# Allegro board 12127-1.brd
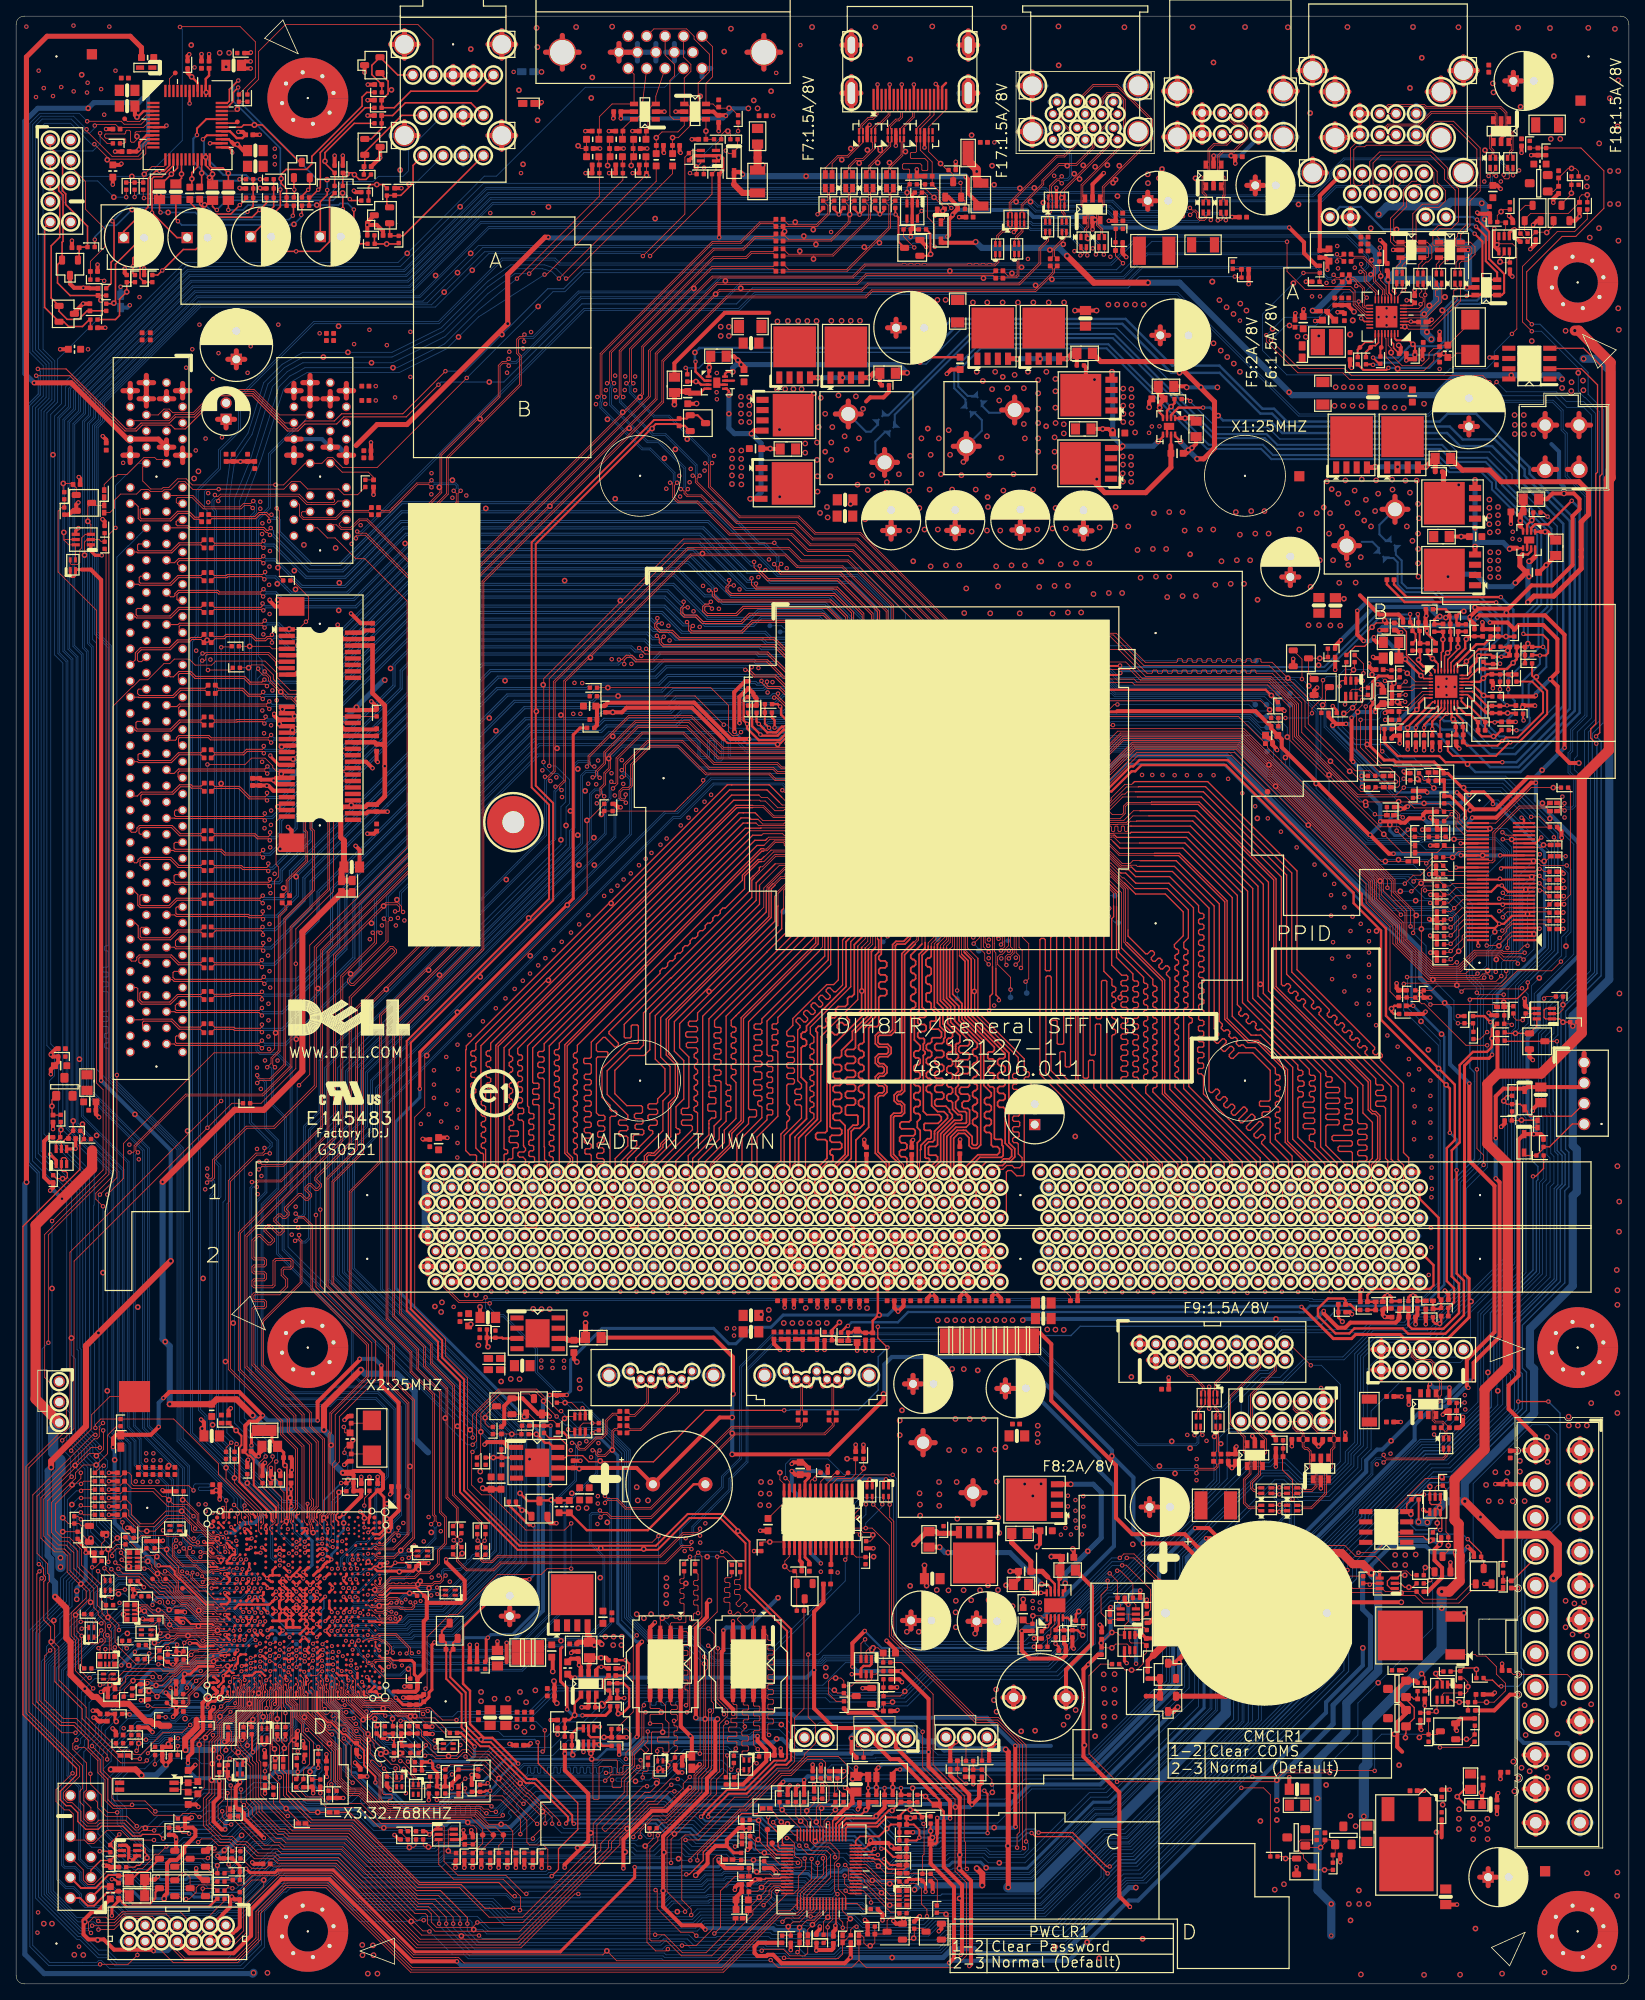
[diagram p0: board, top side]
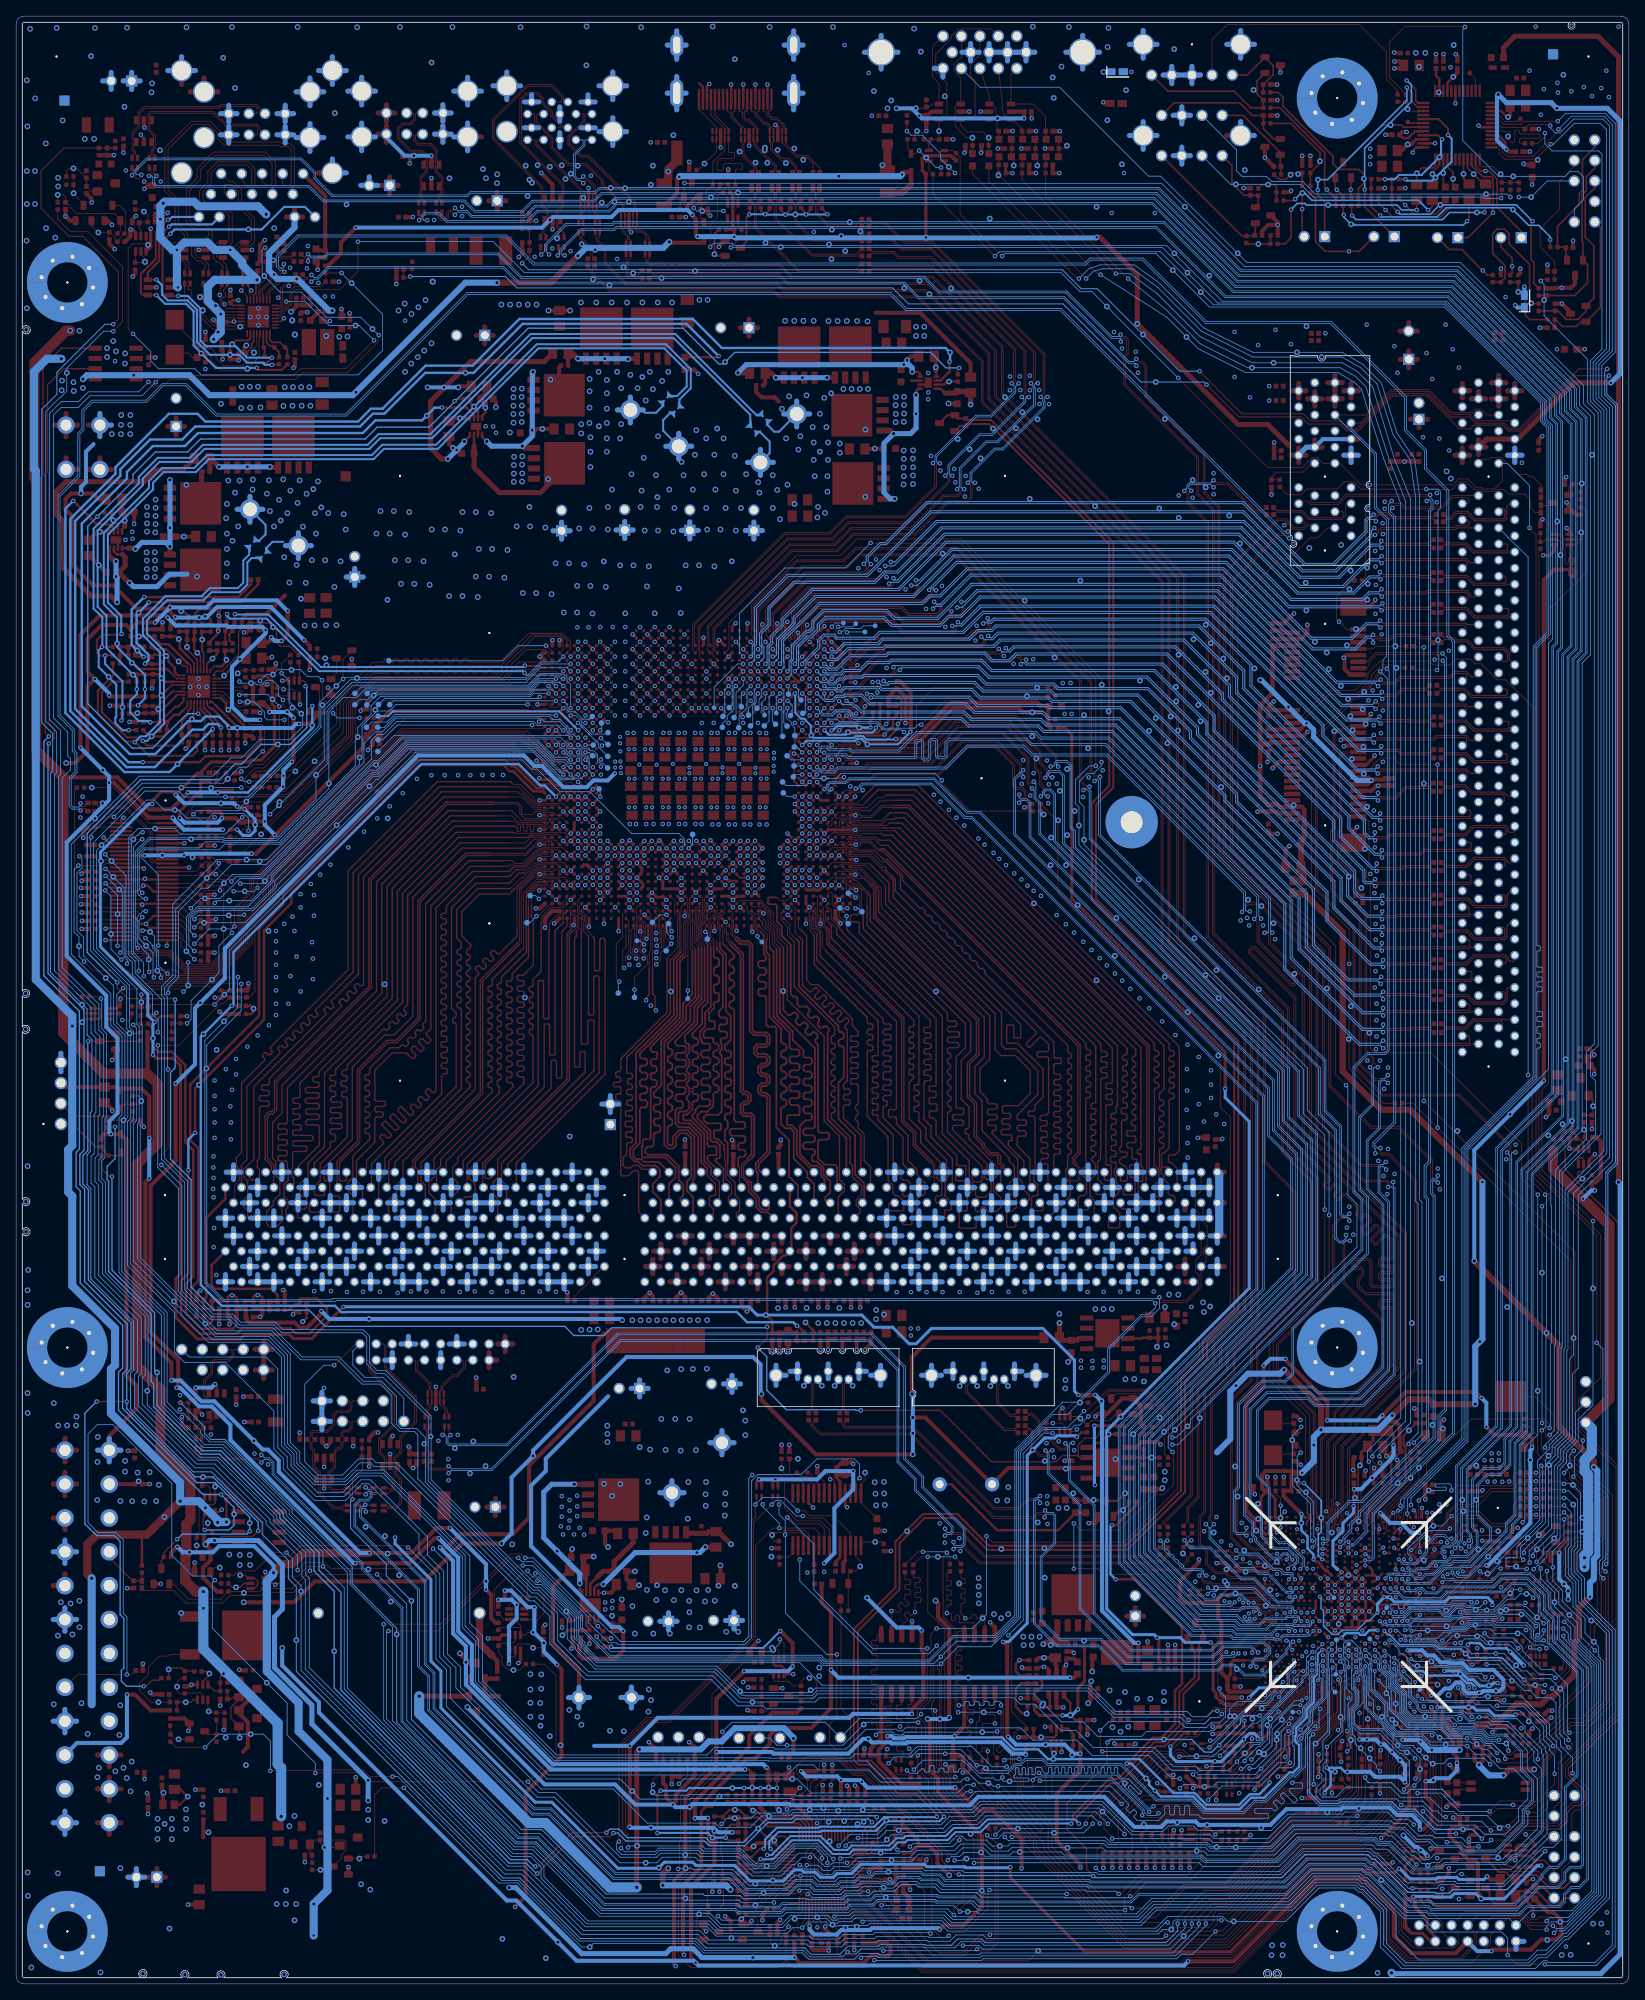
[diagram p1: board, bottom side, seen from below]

Outline 200 x 244 mm; copper layers: TOP, L2VCC, L3, BOTTOM. Coordinates in mm from the lower left corner of the outline.
Outline path: 0,243 0,1 arc(0.29,0.29) 1,0 199,0 arc(199.71,0.29) 200,1 200,243 arc(199.71,243.71) 199,244 1,244 arc(0.29,243.71) 0,243

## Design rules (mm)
net group 5MIL: nets ANTI-POP_GPIO1 EAPD_DEPOP
net group 6MIL: nets DDSP_D_TX_N0 DDSP_D_TX_N2
net group AUDIO-10: nets MIC1_VREFO_L MIC1_VREFO_R
net group CK_96M_DREF-DIFF: nets CK_96M_DREF_DN CK_96M_DREF_DP
net group CK_100M_CPU_XDP_DN: nets CK_100M_CPU_XDP_DN CK_XDP_S_DN
net group CK_100M_CPU_XDP_DP: nets CK_100M_CPU_XDP_DP CK_XDP_S_DP
net group CK_100M_DMI-DIFF: nets 100M_DMI_PCH_DN 100M_DMI_PCH_DP
net group CK_CSI_PCH-DIFF1: nets CK_CSI_PCH_IN_DN CK_CSI_PCH_IN_DP
net group CK_SATA_PCH-DIFF1: nets CK_SATA_PCH_DN CK_SATA_PCH_DP
net group DMI-8: nets DMIRCOMP XCLK_RCOMP
net group EXP_A_TX_0_C_DN: nets EXP_A_TX_0_C_DN EXP_A_TX_DN0
net group EXP_A_TX_0_C_DP: nets EXP_A_TX_0_C_DP EXP_A_TX_DP0
net group EXP_A_TX_1_C_DN: nets EXP_A_TX_1_C_DN EXP_A_TX_DN1
net group EXP_A_TX_1_C_DP: nets EXP_A_TX_1_C_DP EXP_A_TX_DP1
net group EXP_A_TX_2_C_DN: nets EXP_A_TX_2_C_DN EXP_A_TX_DN2
net group EXP_A_TX_2_C_DP: nets EXP_A_TX_2_C_DP EXP_A_TX_DP2
net group EXP_A_TX_3_C_DN: nets EXP_A_TX_3_C_DN EXP_A_TX_DN3
net group EXP_A_TX_3_C_DP: nets EXP_A_TX_3_C_DP EXP_A_TX_DP3
net group EXP_A_TX_4_C_DN: nets EXP_A_TX_4_C_DN EXP_A_TX_DN4
net group EXP_A_TX_4_C_DP: nets EXP_A_TX_4_C_DP EXP_A_TX_DP4
net group EXP_A_TX_5_C_DN: nets EXP_A_TX_5_C_DN EXP_A_TX_DN5
net group EXP_A_TX_5_C_DP: nets EXP_A_TX_5_C_DP EXP_A_TX_DP5
net group EXP_A_TX_6_C_DN: nets EXP_A_TX_6_C_DN EXP_A_TX_DN6
net group EXP_A_TX_6_C_DP: nets EXP_A_TX_6_C_DP EXP_A_TX_DP6
net group EXP_A_TX_7_C_DN: nets EXP_A_TX_7_C_DN EXP_A_TX_DN7
net group EXP_A_TX_7_C_DP: nets EXP_A_TX_7_C_DP EXP_A_TX_DP7
net group EXP_A_TX_8_C_DN: nets EXP_A_TX_8_C_DN EXP_A_TX_DN8
net group EXP_A_TX_8_C_DP: nets EXP_A_TX_8_C_DP EXP_A_TX_DP8
net group EXP_A_TX_9_C_DN: nets EXP_A_TX_9_C_DN EXP_A_TX_DN9
net group EXP_A_TX_9_C_DP: nets EXP_A_TX_9_C_DP EXP_A_TX_DP9
net group EXP_A_TX_10_C_DN: nets EXP_A_TX_10_C_DN EXP_A_TX_DN10
net group EXP_A_TX_10_C_DP: nets EXP_A_TX_10_C_DP EXP_A_TX_DP10
net group EXP_A_TX_11_C_DN: nets EXP_A_TX_11_C_DN EXP_A_TX_DN11
net group EXP_A_TX_11_C_DP: nets EXP_A_TX_11_C_DP EXP_A_TX_DP11
net group EXP_A_TX_12_C_DN: nets EXP_A_TX_12_C_DN EXP_A_TX_DN12
net group EXP_A_TX_12_C_DP: nets EXP_A_TX_12_C_DP EXP_A_TX_DP12
net group EXP_A_TX_13_C_DN: nets EXP_A_TX_13_C_DN EXP_A_TX_DN13
net group EXP_A_TX_13_C_DP: nets EXP_A_TX_13_C_DP EXP_A_TX_DP13
net group EXP_A_TX_14_C_DN: nets EXP_A_TX_14_C_DN EXP_A_TX_DN14
net group EXP_A_TX_14_C_DP: nets EXP_A_TX_14_C_DP EXP_A_TX_DP14
net group EXP_A_TX_15_C_DN: nets EXP_A_TX_15_C_DN EXP_A_TX_DN15
net group EXP_A_TX_15_C_DP: nets EXP_A_TX_15_C_DP EXP_A_TX_DP15
net group FAN_SYS-6.5: nets SYS_FAN_CTRL_SIO SYS_FAN_TACH_SIO
net group LAN_MDI1_C-DIFF1: nets LAN_MDI1_DN_C LAN_MDI1_DP_C
net group MG-CK-DP: nets CK_DP_DN CK_DP_DP
net group MG-CK_DPNS_R: nets CK_DPNS_R_DN CK_DPNS_R_DP
net group MG-CK_GLAN: nets CK_GLAN_DN CK_GLAN_DP
net group MG-CK_PCIE_1PCIEX1: nets CK_PCIE_1PCIEX1_DN CK_PCIE_1PCIEX1_DP
net group MG-CK_PCIEX1_WLAN: nets CK_PCIEX1_WLAN_DN CK_PCIEX1_WLAN_DP
net group MG-CK_PE_100M_16PORT: nets CK_PE_100M_16PORT_DN CK_PE_100M_16PORT_DP
net group MG-CK_PE_100M_MCP: nets CK_PE_100M_MCP_DN CK_PE_100M_MCP_DP
net group MG-DDR-A-DQS0: nets M_DQS_A_DN0 M_DQS_A_DP0
net group MG-DDR-A-DQS1: nets M_DQS_A_DN1 M_DQS_A_DP1
net group MG-DDR-A-DQS2: nets M_DQS_A_DN2 M_DQS_A_DP2
net group MG-DDR-A-DQS3: nets M_DQS_A_DN3 M_DQS_A_DP3
net group MG-DDR-A-DQS4: nets M_DQS_A_DN4 M_DQS_A_DP4
net group MG-DDR-A-DQS5: nets M_DQS_A_DN5 M_DQS_A_DP5
net group MG-DDR-A-DQS6: nets M_DQS_A_DN6 M_DQS_A_DP6
net group MG-DDR-A-DQS7: nets M_DQS_A_DN7 M_DQS_A_DP7
net group MG-DDR-B-DQ0: nets M_DQS_B_DN0 M_DQS_B_DP0
net group MG-DDR-B-DQ1: nets M_DQS_B_DN1 M_DQS_B_DP1
net group MG-DDR-B-DQ2: nets M_DQS_B_DN2 M_DQS_B_DP2
net group MG-DDR-B-DQ3: nets M_DQS_B_DN3 M_DQS_B_DP3
net group MG-DDR-B-DQ4: nets M_DQS_B_DN4 M_DQS_B_DP4
net group MG-DDR-B-DQ5: nets M_DQS_B_DN5 M_DQS_B_DP5
net group MG-DDR-B-DQ6: nets M_DQS_B_DN6 M_DQS_B_DP6
net group MG-DDR-B-DQ7: nets M_DQS_B_DN7 M_DQS_B_DP7
net group MG-LAN0: nets LAN_MDI0_DN LAN_MDI0_DP
net group MG-LAN1: nets LAN_MDI1_DN LAN_MDI1_DP
net group MG-LAN2: nets LAN_MDI2_DN LAN_MDI2_DP
net group MG-LAN3: nets LAN_MDI3_DN LAN_MDI3_DP
net group MG-LAN-MDI3: nets LAN_MDI3_DN_C LAN_MDI3_DP_C
net group MG-LAN_MDI1: nets LAN_MDI0_DN_C LAN_MDI0_DP_C
net group MG-LAN_MDI2: nets LAN_MDI2_DN_C LAN_MDI2_DP_C
net group MG-PCIE-RX-0: nets EXP_A_RX_DN0 EXP_A_RX_DP0
net group MG-PCIE-RX-1: nets EXP_A_RX_DN1 EXP_A_RX_DP1
net group MG-PCIE-RX-2: nets EXP_A_RX_DN2 EXP_A_RX_DP2
net group MG-PCIE-RX-3: nets EXP_A_RX_DN3 EXP_A_RX_DP3
net group MG-PCIE-RX-4: nets EXP_A_RX_DN4 EXP_A_RX_DP4
net group MG-PCIE-RX-5: nets EXP_A_RX_DN5 EXP_A_RX_DP5
net group MG-PCIE-RX-6: nets EXP_A_RX_DN6 EXP_A_RX_DP6
net group MG-PCIE-RX-7: nets EXP_A_RX_DN7 EXP_A_RX_DP7
net group MG-PCIE-RX-8: nets EXP_A_RX_DN8 EXP_A_RX_DP8
net group MG-PCIE-RX-9: nets EXP_A_RX_DN9 EXP_A_RX_DP9
net group MG-PCIE-RX-10: nets EXP_A_RX_DN10 EXP_A_RX_DP10
net group MG-PCIE-RX-11: nets EXP_A_RX_DN11 EXP_A_RX_DP11
net group MG-PCIE-RX-12: nets EXP_A_RX_DN12 EXP_A_RX_DP12
net group MG-PCIE-RX-13: nets EXP_A_RX_DN13 EXP_A_RX_DP13
net group MG-PCIE-RX-14: nets EXP_A_RX_DN14 EXP_A_RX_DP14
net group MG-PCIE-RX-15: nets EXP_A_RX_DN15 EXP_A_RX_DP15
net group MINI_CARD-4: nets MINI_CLKREQ#_WLAN MINI_CLKREQ#_WLAN_C
net group POWER_CPU_10_5-10: nets V_1P05_PECI_VCOM V_VCCIOA_LOAD
net group PWM_CSN4: nets PWM_CSN4 VCC
net group SIO_GND: nets SIO_VIN0 SIO_VIN1
net group 5MIL-1: nets +5V_VGA V_5P0_CONN_CRT_L V_5P0_HDMI_CONN V_5P0_HDMI_CONN_L
net group 6.5MS: nets M_CAS_A_N M_MAA_A0 M_MAA_A1 M_MAA_A2 M_MAA_A3 M_MAA_A4 M_MAA_A5 M_MAA_A6 M_MAA_A7 M_MAA_A8 M_MAA_A9 M_MAA_A10 M_MAA_A11 M_MAA_A12 M_MAA_A13 M_MAA_A14 M_MAA_A15 M_RAS_A_N M_SBS_A0 M_SBS_A1 M_SBS_A2 M_WE_A_N
net group 7MIL: nets FP_AUD_DETECT
net group 7MIL-1: nets FWH_ID0 INIT_3V L_AD0 L_AD0_R L_AD1 L_AD1_R L_AD2 L_AD2_R L_AD3 L_AD3_R L_FRAME_N L_FRAME_N_R LPC_DRQ0_N LPC_DRQ1_N SER_IRQ
net group 8MIL: nets SLP_SUS_FET SLP_SUS_FET_L SLP_SUSB SLP_SUSB_L_2 SUS_WARN_5VDUAL SUS_WARN_5VDUAL_L SUS_WARNB SUS_WARNB_L SUS_WARNB_R SUSACK_N
net group 9.5MS: nets M_ODT_A0 M_ODT_A1 M_SCKE_A0 M_SCKE_A1 M_SCS_A_N0 M_SCS_A_N1
net group 9.5MS-1: nets M_ODT_B0 M_ODT_B1 M_SCKE_B0 M_SCKE_B1 M_SCS_B_N0 M_SCS_B_N1
net group 10MIL: nets AUD_LINK_BCLK AUD_LINK_BCLK_R AUD_LINK_RST_N AUD_LINK_RST_R_N AUD_LINK_SDIN AUD_LINK_SDIN_1 AUD_LINK_SDO AUD_LINK_SDO_R AUD_LINK_SDO_R1 AUD_LINK_SYNC AUD_LINK_SYNC_R COPEN* CPU_THERMDA FRONT_JD LINE2_JD LINEIN_JD MIC1_JD MIC2_JD SENSE_A SENSE_B SYS_TEMP_SIO TSD-_1 TSD-_2
net group 12MIL: nets DIMM_CA_CPU_VREF_A DIMM_CA_CPU_VREF_RC DIMM_CA_VREF_A DIMM_CA_VREF_A_L DIMM_DQ_CPU_VREF_A DIMM_DQ_VREF_A DIMM_DQ_VREF_A_L DMI_IT_MR_DN0 DMI_IT_MR_DN1 DMI_IT_MR_DN2 DMI_IT_MR_DN3 DMI_IT_MR_DP0 DMI_IT_MR_DP1 DMI_IT_MR_DP2 DMI_IT_MR_DP3 DMI_MT_IR_DN0 DMI_MT_IR_DN1 DMI_MT_IR_DN2 DMI_MT_IR_DN3 DMI_MT_IR_DP0 DMI_MT_IR_DP1 DMI_MT_IR_DP2 DMI_MT_IR_DP3 FDI_TX_DN0 FDI_TX_DN1 FDI_TX_DP0 FDI_TX_DP1 USB_EXT2_DN10 USB_EXT2_DN11 USB_EXT2_DP10 USB_EXT2_DP11 USB_EXT_DN0 USB_EXT_DN1 USB_EXT_DN2 USB_EXT_DN3 USB_EXT_DN4 USB_EXT_DN8 USB_EXT_DN9 USB_EXT_DN10 USB_EXT_DN11 USB_EXT_DP0 USB_EXT_DP1 USB_EXT_DP2 USB_EXT_DP3 USB_EXT_DP4 USB_EXT_DP8 USB_EXT_DP9 USB_EXT_DP10 USB_EXT_DP11 USB_PCH_DN0 USB_PCH_DN1 USB_PCH_DN2 USB_PCH_DN3 USB_PCH_DN4 USB_PCH_DN5 USB_PCH_DN8 USB_PCH_DN9 USB_PCH_DN10 USB_PCH_DN11 USB_PCH_DP0 USB_PCH_DP1 USB_PCH_DP2 USB_PCH_DP3 USB_PCH_DP4 USB_PCH_DP5 USB_PCH_DP8 USB_PCH_DP9 USB_PCH_DP10 USB_PCH_DP11
net group 15MIL: nets DDSP_C_TX_DN_0 DDSP_C_TX_DN_1 DDSP_C_TX_DN_2 DDSP_C_TX_DN_3 DDSP_C_TX_DP_0 DDSP_C_TX_DP_1 DDSP_C_TX_DP_2 DDSP_C_TX_DP_3 HDMI_LANE0_DN HDMI_LANE0_DN_C HDMI_LANE0_DP HDMI_LANE0_DP_C HDMI_LANE1_DN HDMI_LANE1_DN_C HDMI_LANE1_DP HDMI_LANE1_DP_C HDMI_LANE2_DN HDMI_LANE2_DN_C HDMI_LANE2_DP HDMI_LANE2_DP_C HDMI_LANE3_DN HDMI_LANE3_DN_C HDMI_LANE3_DP HDMI_LANE3_DP_C HSI_DN3 HSI_DN4 HSI_DN5 HSI_DP3 HSI_DP4 HSI_DP5 HSI_LAN_DN4_R HSI_LAN_DP4_R HSO_C_DN3 HSO_C_DN4 HSO_C_DN5 HSO_C_DP3 HSO_C_DP4 HSO_C_DP5 HSO_C_LAN_DN4 HSO_C_LAN_DP4 HSO_DN3 HSO_DN5 HSO_DP3 HSO_DP5 TPEV_CFG_RCOMP
net group 18.5MS: nets M_DATA_A0 M_DATA_A1 M_DATA_A2 M_DATA_A3 M_DATA_A4 M_DATA_A5 M_DATA_A6 M_DATA_A7 M_DATA_A8 M_DATA_A9 M_DATA_A10 M_DATA_A11 M_DATA_A12 M_DATA_A13 M_DATA_A14 M_DATA_A15 M_DATA_A16 M_DATA_A17 M_DATA_A18 M_DATA_A19 M_DATA_A20 M_DATA_A21 M_DATA_A22 M_DATA_A23 M_DATA_A24 M_DATA_A25 M_DATA_A26 M_DATA_A27 M_DATA_A28 M_DATA_A29 M_DATA_A30 M_DATA_A31 M_DATA_A32 M_DATA_A33 M_DATA_A34 M_DATA_A35 M_DATA_A36 M_DATA_A37 M_DATA_A38 M_DATA_A39 M_DATA_A40 M_DATA_A41 M_DATA_A42 M_DATA_A43 M_DATA_A44 M_DATA_A45 M_DATA_A46 M_DATA_A47 M_DATA_A48 M_DATA_A49 M_DATA_A50 M_DATA_A51 M_DATA_A52 M_DATA_A53 M_DATA_A54 M_DATA_A55 M_DATA_A56 M_DATA_A57 M_DATA_A58 M_DATA_A59 M_DATA_A60 M_DATA_A61 M_DATA_A62 M_DATA_A63
net group 20MIL: nets BLUE_CRT CSN1 CSN2 CSN3 CSP1 CSP2 CSP3 FRONT_USB3_RX2+ FRONT_USB3_RX2- FRONT_USB3_TX2+ FRONT_USB3_TX2- GREEN_CRT REAR_USB3_RX0+ REAR_USB3_RX0- REAR_USB3_RX1+ REAR_USB3_RX1- REAR_USB3_TX0+ REAR_USB3_TX0- REAR_USB3_TX1+ REAR_USB3_TX1- RED_CRT SATA_RXN0_C SATA_RXN1_C SATA_RXP0_C SATA_RXP1_C SATA_TXN0_C SATA_TXN1_C SATA_TXP0_C SATA_TXP1_C SATAHDR_RX_DN0 SATAHDR_RX_DN1 SATAHDR_RX_DP0 SATAHDR_RX_DP1 SATAHDR_TX_DN0 SATAHDR_TX_DN1 SATAHDR_TX_DP0 SATAHDR_TX_DP1 USB3_RX0_DN USB3_RX0_DP USB3_RX1_DN USB3_RX1_DP USB3_RX2_DN USB3_RX2_DN_P USB3_RX2_DP USB3_RX2_DP_P USB3_TX0_C_DN USB3_TX0_C_DP USB3_TX0_EMI_DN USB3_TX0_EMI_DP USB3_TX1_C_DN USB3_TX1_C_DP USB3_TX1_EMI_DN USB3_TX1_EMI_DP USB3_TX2_C_DN USB3_TX2_C_DN_P USB3_TX2_C_DP USB3_TX2_C_DP_P USB3_TX2_EMI_DN USB3_TX2_EMI_DP VCC_SENSE VGA_BLUE VGA_BLUE_C_L VGA_GREEN VGA_GREEN_C_L VGA_RED VGA_RED_C_L VSS_SENSE
net group 40MIL: nets MEM_LX PWM1_LX PWM2_LX PWM3_LX
net group AUDIO-8: nets AUD_IN_L AUD_IN_LL AUD_IN_LL_1 AUD_IN_R AUD_IN_RR AUD_IN_RR_1 AUD_MIC2_L AUD_MIC2_L_C AUD_MIC2_R AUD_MIC2_R_C AUD_MIC_2L AUD_MIC_2R AUDAMPIN_L AUDAMPIN_L_C AUDAMPIN_R AUDAMPIN_R_C AUDIN_L AUDIN_R FB_AUDOUT_L FB_AUDOUT_R FB_AUDOUTR_L FB_AUDOUTR_R FP_MIC1_L FP_MIC1_LL FP_MIC1_LL_1 FP_MIC1_R FP_MIC1_RR FP_MIC1_RR_1 FP_MICVREF_D1 FP_MICVREF_D2 FP_OUT_L FP_OUT_L_C FP_OUT_R FP_OUT_R_C FP_OUTR_L FP_OUTR_LL FP_OUTR_R FP_OUTR_RR LINE2_VREFO MIC1_L MIC1_R MIC2-VREFO MIC2_LL MIC2_RR
net group CLOCK-4: nets CK_14M_FLEX3 CK_14M_TPM CK_33M_PCI0 CK_33M_PCI1 CK_33M_PCI2 CK_33M_PCI3 CK_48M_PCH CK_48M_SIO2 CK_P_33M_LPCP80 CK_P_33M_SIO CK_P_33M_TPM CK_PCH_33M_FB CK_REFCLK_PCH SUSCLK
net group CPU-4: nets DISP_UTIL_CPU H_PM_SYNC_0 H_PRDY_N H_PREQ_N H_SKTOCC_N H_TCK H_TDI H_TDO H_TMS H_TRST_N HSW_PCUDEBUG_0 HSW_PCUDEBUG_1 HSW_PCUDEBUG_2 HSW_PCUDEBUG_3 HSW_PCUDEBUG_4 HSW_PCUDEBUG_5 HSW_PCUDEBUG_6 HSW_PCUDEBUG_7 HSW_PCUDEBUG_8 HSW_PCUDEBUG_9 HSW_PCUDEBUG_10 HSW_PCUDEBUG_11 HSW_PCUDEBUG_12 HSW_PCUDEBUG_13 HSW_PCUDEBUG_14 HSW_PCUDEBUG_15 HSW_PCUSTB_0_DN HSW_PCUSTB_0_DP HSW_PCUSTB_1_DN HSW_PCUSTB_1_DP HSW_STRAP_13 HSW_XDP_MBP_0 HSW_XDP_MBP_1 PRIVACY_MSR_EN_N PWR_DEBUG TESTLOW_1 TESTLOW_2 VCCST_PWRGD XDP_PWR_DEBUG
net group DDR3_B-6.5MW: nets M_DATA_B0 M_DATA_B1 M_DATA_B2 M_DATA_B3 M_DATA_B4 M_DATA_B5 M_DATA_B6 M_DATA_B7 M_DATA_B8 M_DATA_B9 M_DATA_B10 M_DATA_B11 M_DATA_B12 M_DATA_B13 M_DATA_B14 M_DATA_B15 M_DATA_B16 M_DATA_B17 M_DATA_B18 M_DATA_B19 M_DATA_B20 M_DATA_B21 M_DATA_B22 M_DATA_B23 M_DATA_B24 M_DATA_B25 M_DATA_B26 M_DATA_B27 M_DATA_B28 M_DATA_B29 M_DATA_B30 M_DATA_B31 M_DATA_B32 M_DATA_B33 M_DATA_B34 M_DATA_B35 M_DATA_B36 M_DATA_B37 M_DATA_B38 M_DATA_B39 M_DATA_B40 M_DATA_B41 M_DATA_B42 M_DATA_B43 M_DATA_B44 M_DATA_B45 M_DATA_B46 M_DATA_B47 M_DATA_B48 M_DATA_B49 M_DATA_B50 M_DATA_B51 M_DATA_B52 M_DATA_B53 M_DATA_B54 M_DATA_B55 M_DATA_B56 M_DATA_B57 M_DATA_B58 M_DATA_B59 M_DATA_B60 M_DATA_B61 M_DATA_B62 M_DATA_B63
net group DDR3_B-8.5MW: nets M_CAS_B_N M_MAA_B0 M_MAA_B1 M_MAA_B2 M_MAA_B3 M_MAA_B4 M_MAA_B5 M_MAA_B6 M_MAA_B7 M_MAA_B8 M_MAA_B9 M_MAA_B10 M_MAA_B11 M_MAA_B12 M_MAA_B13 M_MAA_B14 M_MAA_B15 M_RAS_B_N M_SBS_B0 M_SBS_B1 M_SBS_B2 M_WE_B_N
net group DDR3_B-12: nets DIMM_DQ_CPU_VREF_B DIMM_DQ_CPU_VREF_B_RC DIMM_DQ_CPU_VREF_RC DIMM_DQ_VREF_B DIMM_DQ_VREF_B_L
net group DDR_RCOMP-12: nets DDR_RCOMP_0 DDR_RCOMP_1 DDR_RCOMP_2
net group DISPLAY-4: nets 5VDDCCL 5VDDCCL_R 5VDDCDA 5VDDCDA_R DDPC_CTRL_CLK DDPC_CTRL_CLK_CONN DDPC_CTRL_DATA DDPC_CTRL_DATA_CONN DDSP_C_HPD DDSP_C_HPD_CONN VCC5_DDC_HDMI VGA_DACREFSET VGA_DDC_PU VGA_HSYNC_3V VGA_HSYNC_3V_L VGA_HSYNC_3V_R VGA_PCH_DDCSCL VGA_PCH_DDCSDA VGA_VSYNC_3V VGA_VSYNC_3V_L VGA_VSYNC_3V_R
net group DP_COMP-12: nets DP_COMP
net group DUAL_POWER-6.5: nets 5VDUAL_NCH 5VDUAL_PCH 5VDUAL_PCH_R BL_CUT2 BV_5VDUAL_BACKFEED_CUT_L BV_Q49_PIN5 DUAL_V_1 DUAL_V_AND DUAL_V_AND_R DUAL_V_U DUAL_V_U_AND DUAL_V_U_INV_R L_BACKFEED_CUT LATCHED_BACKFEED_CUT MINI_POWER_CTRL MINI_POWER_CTRL_1 MINI_POWER_CTRL_2 MINI_POWER_CTRL_3 VREG_PCIAUX_PCH_1
net group FAN_CPU-6.5: nets CPU_FAN_CTRL_CONN CPU_FAN_CTRL_SIO CPU_FAN_TACH_1 CPU_FAN_TACH_L CPU_FAN_TACH_SIO
net group FDI-4: nets FDI_INT
net group FDI-8: nets FDI_RCOMP
net group GND-20: nets AGND AUD_REGREF AUDIO_VREF CPU_VSS_T8 GND JDREF SIO_GND V_1P5_STBY_INT
net group GPIO_4: nets W1_DETECT_USB_R
net group GPIO_4-4: nets BOARD_ID_0 BOARD_ID_1 BT_RADIO_CL CHASSIS_ID_0 CHASSIS_ID_1 DUAL_V FB_USBF1_DET FB_USBF2_DET FDI_CSYNC FP_AUDIO_PRESENCE*_C HDMI_DETECT IGC_EN_N IO_SMI_N LAN_DISABLE_N LANCLK_REQ_N LANCLK_REQ_U_N LANWAKE_N LATCHED_BACKFEED_CUT_R LPC_PME_N ME_CNTL ME_CNTL_1 ME_CNTL_2 MTST_ID P_PME# PCH_CONFIG_JUMPER PCH_GP69 PCH_GPIO16 PCIEX1_PRSNT2_N PECI_REQ_N PW_CLEAR QF2_1 QF2_2 RST1# SATA1GP SATA2GP SATA3GP SOP_ENABLE_GP33 SST_CTL_R TD_IREF USB_PWR_CRL1 USB_PWR_CRL1_B1 USB_PWR_CRL2 USB_PWR_CRL2_B1 VGA_DET W1_DETECT_USB WIFI_RF_EN
net group KBMS-4: nets KCLK KDAT MCLK MDAT
net group LAN-4: nets RTL_ISOLATE RTL_ISOLATE_N RTL_ISOLATE_R
net group LAN-10: nets LAN_RSET
net group LAN-10.5: nets LINK_ACTIVITY LINK_ACTIVITY_N SPEED_100 SPEED_100_N SPEED_1000 SPEED_1000_N
net group MG-DDR-A-CLK: nets CK_M_DDR0_A_DP CK_M_DDR1_A_DN CK_M_DDR1_A_DP
net group MG-DDR-A-CTRL-CLK: nets CK_M_DDR0_A_DN
net group MG-DDR-B-CLK: nets CK_M_DDR0_B_DP CK_M_DDR1_B_DN CK_M_DDR1_B_DP
net group MG-DDR-B-CTRL-CLK: nets CK_M_DDR0_B_DN
net group MSATA-4: nets CLINK_CLK CLINK_DATA CLINK_RST_N
net group OSCILLATION-4: nets LAN_XTALI LAN_XTALO PCH_RTCRST_DOWN PCH_RTCX1 PCH_RTCX2 XTAL_25M_PCH_IN XTAL_25M_PCH_OUT
net group PCH-4: nets CPU_THERMTRIP_N DSWVRMEN FP_RST_DBR_N FP_RST_PCH_N H_THERMTRIP_N KBRST_N MINI1_WAKE# PCH_GP8 PCH_GP15 PCH_GP44 PCH_GP45 PCH_GP70_PU PCH_GP71_PU PCH_GP72_PU PCH_GP74_PU PCH_INTRUDER_N PCH_INTVRMEN PCH_MEPWROK_R PCH_RI PCH_RTCRST_PULLUP PCH_SIO_DPWROK PCH_SIO_DPWROK_1 PCH_SRTCRSTB_PULLUP PCH_SYSPWROK PCIEX16_PRSNT2_N PLTRST_MINI_N PWRGD_3V RSMRST* RSMRST*_R RSMRST_SIO_N SB_PWR_ON_R SW_ON_N VR_READY WAKE_N XDP_PLTRST_N XDP_VR_READY
net group PCI-4: nets P_GNT_N1 P_GNT_N2 P_GNT_N3 P_INTA_N P_INTB_N P_INTC_N P_INTD_N P_INTH_N P_REQ_N1 P_REQ_N2 P_REQ_N3
net group PCI-8: nets PCIE_RCOMP
net group PECI-4: nets H_PECI PECI_PCH PECI_SIO_R
net group PEG_COMP-12: nets PEG_COMP
net group POWER_10_5-10: nets SIO_VIN2 SIO_VIN2_1 SIO_VIN3 SIO_VIN3_1
net group POWER_20_5-20: nets V_1P05_DSW_INT_C V_1P05_DSW_INT_R V_1P05_XCK_DCB_FB_R V_3P3_BG
net group POWER_35_5-35: nets AUD_AVDD VBAT1 VBAT1_R VBAT2
net group POWER_40_5-40: nets 1D5V_S0_EP/SP 1P5V_AUX LAN_CONN_CVT MEM_VIN V_1P5_PCH V_3P0_BAT_VREG V_3P3_EPW V_3P3_LAN_VDDSREG VCC3_3SBREF
net group POWER_50_5-50: nets 5V_DUAL 5VDUAL_USB_F 5VDUAL_USB_R +12V -12V HWM_REF SB3V SB5V SIO_VIN0_1 SIO_VIN1_1 SIO_VIN4 USBVCC01 USBVCC23 USBVCC45 USBVCC89 USBVCC1011 V_1P05_LAN V_1P05_PCH V_1P05V V_3P3_A V_3P3_LAN V_3P3_PCIVAUX V_5_CODEC V_5P0_A V_CPU_CORE V_SM V_SM_1 V_SM_VTT VCC3 VCC12CPU
net group POWER_50_5_V: nets U17_VCC
net group POWER_60_5-60: nets LAN_1P05_OUT
net group POWER_CPU_20_5-20: nets V_1P5_DAC_FB V_1P5_DAC_FB_R V_CPU_VCCIO2PCH V_CPU_VCCIO_RIGHT VCCIO2PCH VCCST
net group PWM_6_12-6.5: nets DRVON
net group PWM_12_12-12: nets 1P05_PCH_DRV_1 1P05_PCH_EN 1P5_PCH_EN 1P05_PCH_FB 1P5_PCH_FB 1P05_PCH_S1 1P05_PCH_S1_U 1P05_PCH_SS 5337_VREF 81102_COMP 81102_COMP_1 81102_COMP_2 81102_CSCCOMP 81102_CSCM_1 81102_CSREF 81102_CSSUM 81102_DIFF 81102_FB 81102_ILIM 81102_IOUT 81102_RAMP 81102_TSENSE 81102_TSENSE_R 81102_VCC 81102_VSN 81102_VSP ADDR CSP1_R CSP2_R CSP3_R DDR_SHDN IMAX MEM_COMP_3 MEM_CS MEM_FB MEM_RF PWM1_EN PWM2_EN PWM3_EN ROSC
net group PWM_20_20-20: nets MEM_BOOT MEM_BOOT_1 MEM_SNB PWM1_BT PWM1_BT_1 PWM1_SNB PWM2_BT PWM2_BT_1 PWM2_SNB PWM3_BT PWM3_BT_1 PWM3_SNB VBOOT
net group PWM_25-25: nets 1P05_PCH_DRV 1P05_PCH_G 5337_CTRL MEM_HG MEM_HG_1 MEM_LG MEM_VCC PWM1_HG PWM1_HG_1 PWM1_LG PWM1_VCC PWM2_HG PWM2_HG_1 PWM2_LG PWM2_VCC PWM3_HG PWM3_HG_1 PWM3_LG PWM3_VCC
net group PWR_LED-4: nets PWR_LEDJ2 PWR_LEDJ3 SIO_PWRLED_N SIO_SUSLED_N SUS_LED4 SUS_LED5 SUS_LED6
net group PWR_LED-10: nets HD_LED_PWR1 LED_L PWR_LED_G PWR_LED_Y
net group PWRGD&RST-4: nets 1P05_PCH_EN_R 1P5_PCH_EN_R 1P5_PCH_EN_R_1 BL_CUT1 BL_CUT3 DDR3_DRAMRST_N GPIO_PCIE_RESET H_CPURST_N H_DRAMPWRGD H_DRAMPWRGD_CPU H_PWRGD H_RSTOUT_XDP_N H_SKTOCC_VCORE L_PWRDWN_N MEM_EN MEM_PG PCIRST1# PCIRST3# PLTRST*_LPC PLTRST_CPU_N PLTRST_LAN_N PLTRST_N PLTRST_PCIE_SLOTS_N PLTRST_PEG_PCIE_SLOTS_N PLTRST_PEG_SLOTS_N PLTRST_SL_X1_N PLTRST_TPM_N PSPWRGD PSPWRGD_INV PSPWRGD_INV_B1 PSPWRGD_L PWR_BTNJ_C PWRBTN_N PWRGD_3V_B_1 PWROK3 Q37_2 Q37_5 Q37_6 Q44_PIN2 Q46_PIN2 Q46_PIN3 Q46_PIN6 Q48_PIN2 Q48_PIN5 Q51_D Q54_B Q54_C SLP_LAN_B1 SLP_LAN_G2 SLP_LAN_G3 SLP_LAN_N_C SLP_S3_N SLP_S3_N_Q46 SLP_S4_N SLP_S4_N_R SLP_S5_N SLP_WLAN_N SUS_STAT_N V_SM_1P5_EN XDP_DBRESET_N XDP_PWRGD
net group PWRGD&RST-6.5: nets ATX_ON* H_VTTPWRGD H_VTTPWRGD_R
net group PWRGD&RST_4: nets SLP_LAN_B2
net group SATA_COMP-4: nets SATARBIAS_PCH
net group SIO_IT8772-4: nets A20GATE DTR1# GPO50/JP1 PS_ON_N RI1# SIO_EUP_N SIO_SATA_LED SIO_SUSACK_N SIO_VCORE SOUT1 SYS_EUP_CTRL
net group SMBUS-4: nets Q69_GATE Q73_GATE SMB_CLK_MAIN SMB_CLK_RESUME SMB_DATA_MAIN SMB_DATA_RESUME SMLICLK_PCH SMLICLK_PCH_SIO SMLIDATA_PCH SMLIDATA_PCH_SIO SMLINK0_CLK SMLINK0_DATA
net group SPI-4: nets SPI_CLK SPI_CLK_1 SPI_CLK_2 SPI_CS0_N SPI_CS1_N SPI_IO2 SPI_IO3 SPI_MISO SPI_MISO_ROM_1 SPI_MISO_ROM_2 SPI_MOSI SPI_MOSI_1 SPI_MOSI_2 SPI_WP_N_1 SPI_WP_N_2 SST_HOLDJ_1 SST_HOLDJ_2
net group SW_LED-6.5: nets PCH_SATA_LED_N Q62_PIN2 Q62_PIN6 SATA_LED_OUT
net group SYS_POWER-12: nets BZ_ON BZ_ON1 FET_CNTRL_PIN PCH_SPKR1 SPKR V1P05PCH_CNTRL_INPUT V1P05PCH_FET_CNTRL_PINS
net group SYS_POWER-20: nets V_1P5_RTC_INT
net group TP-4: nets P25_GND PCH_GP35 PCH_GP38 PCH_GP48 SLP_A# TCM_BA0 TCM_BA1 TCM_CLK_RUN TCM_NC5# TCM_NCP TP_CPU_G38 TP_CPU_H37 TP_CPU_H38 TP_CPU_J38 TP_CPU_K37 TP_CPU_K39 TP_CPU_M38 TP_CPU_N36 TP_CPU_T35 TP_DISP_J12 TP_DISP_K11 TP_H_CATERR_N TP_PCH_AE30 TP_PCH_AN16 TP_PCH_AT26 TP_PCH_AV22 TP_PCH_P19 TP_PCH_TACH2 TP_PCH_TACH3 TP_PEG_A4 TP_PEG_B3 TP_PEG_C2 TP_PEG_D1 TP_RSVD_AB6 TP_RSVD_AB33 TP_RSVD_AB36 TP_RSVD_AC8 TP_RSVD_AK20 TP_RSVD_AT40 TP_RSVD_AU1 TP_RSVD_AU27 TP_RSVD_AU39 TP_RSVD_AV1 TP_RSVD_AV2 TP_RSVD_AV20 TP_RSVD_AV24 TP_RSVD_AV29 TP_RSVD_AW2 TP_RSVD_AW12 TP_RSVD_AW23 TP_RSVD_AW24 TP_RSVD_AW27 TP_RSVD_AY18 TP_RSVD_C39 TP_RSVD_H12 TP_RSVD_H14 TP_RSVD_H15 TP_RSVD_H16 TP_RSVD_J8 TP_RSVD_J9 TP_RSVD_J10 TP_RSVD_J13 TP_RSVD_J15 TP_RSVD_J16 TP_RSVD_J17 TP_RSVD_J40 TP_RSVD_K8 TP_RSVD_K12 TP_RSVD_K13 TP_RSVD_L10 TP_RSVD_L12 TP_RSVD_M10 TP_RSVD_M11 TP_RSVD_N38 TP_RSVD_P33 TP_RSVD_P37 TP_RSVD_R33 TP_RSVD_R34 TP_RSVD_R36 TP_RSVD_T34 TP_RSVD_U8 TP_RSVD_V7 TP_RSVD_W8 TP_RSVD_Y8 TP_TPM_PIN6 TP_TPM_PIN7 TP_V_1P05_USBSUS_INT
net group USB-5MW: nets USB_OC0_R_N USB_OC1_R_N USB_OC2_R_N USB_OC3_R_N USB_OC4_R_N USB_OC5_R_N USB_OC6_R_N USB_OC7_R_N USB_OC_01* USB_OC_23* USB_OC_45* USB_OC_89* USB_OC_1011* USBRBIAS_PCH
net group VRD_4_12-4: nets H_PROCHOT_N H_PROCHOT_N_R H_PROCHOT_R_N H_VIDALERT_N H_VIDALERT_N_1 H_VIDALERT_N_VR H_VIDSCK H_VIDSCK_VR H_VIDSOUT H_VIDSOUT_VR
net group XDP-4: nets PCH_JTAG_RST_R PCH_JTAG_TCK PCH_JTAG_TDI PCH_JTAG_TDO PCH_JTAG_TMS

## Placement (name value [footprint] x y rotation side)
ATX1  JWT-CONN24B-S-GP  [C4201WV0-2-12P]  191.2 43.08 270 top
ATX12V  TYCO-CONN4B-2GP  [1-1775099-0]  191.72 190.54 180 top
AUDF1  TCN-CONN10A-SFP-1-GP-U  [T11-0061-1A40-4-U]  5.5 223.56 270 top
AUDJK1  AUDIO-JK187-GP  [ABA-JAK-028-K03]  54.19 240.5 0 top
BT1  BAT-AAA-BAT-029-K01-GP  [AAA-BAT-029-P02]  154.82 45.97 180 top
BZ1  HY-05LF-GP  [HY-11H394]  82.22 61.95 0 top
C1  SC10U10V5KX-2GP  [C805H54]  29.67 227.33 90 top
C2  SC22U6D3V5MX-2GP  [C805H58]  29.67 225.37 90 top
C3  SCD1U10V2KX-5GP  [C402H22]  28.91 229.29 90 top
C4  SCD1U10V2KX-5GP  [C402H22]  120.02 228.35 90 top
C5  SC100P50V2JN-3GP  [C402H22]  7.37 215.29 270 top
C6  SC100P50V2JN-3GP  [C402H22]  10.16 209.8 180 top
C7  SC10U10V5KX-2GP  [C805H54]  26.31 222.12 0 top
C8  SC10U10V5KX-2GP  [C805H54]  26.97 237.9 90 top
C9  SCD1U10V2KX-5GP  [C402H22]  92.58 231.65 90 top
C11  SC10U10V5KX-2GP  [C805H54]  24.36 222.12 0 top
C12  SCD1U10V2KX-5GP  [C402H22]  74.55 232.16 270 top
C13  SCD1U10V2KX-5GP  [C402H22]  23.93 237.97 180 top
C14  SC10P50V2JN-4GP  [C402H22]  71.88 229.74 270 top
C15  SC10P50V2JN-4GP  [C402H22]  74.8 229.74 270 top
C16  SC4D7U6D3V3KX-GP  [C603H36]  22.76 222.05 0 top
C17  SCD1U10V2KX-5GP  [C402H22]  22.99 237.97 180 top
C18  SC100P50V2JN-3GP  [C402H22]  79.83 227.97 90 top
C19  SC100P50V2JN-3GP  [C402H22]  81.84 227.97 90 top
C20  SC100P50V2JN-3GP  [C402H22]  87.12 233.17 180 top
C21  SC100P50V2JN-3GP  [C402H22]  85.09 228.73 270 top
C22  SC10P50V2JN-4GP  [C402H22]  77.72 229.74 270 top
C23  SC3D3P50V2CN-GP  [C402H22]  76.96 227.58 90 top
C24  SC3D3P50V2CN-GP  [C402H22]  71.12 227.58 90 top
C25  SC3D3P50V2CN-GP  [C402H22]  74.04 227.58 90 top
C26  SC470P50V2KX-3GP  [C402H22]  111.25 224.16 90 top
C27  SC470P50V2KX-3GP  [C402H22]  113.16 224.16 270 top
C28  SC100P50V2JN-3GP  [C402H22]  43.59 225.35 90 top
C29  SC4D7U6D3V3KX-GP  [C603H36]  21.54 222.02 0 top
C31  SCD1U10V2KX-5GP  [C402H22]  118.24 219.07 270 top
C34  SC3D3P50V2CN-GP  [C402H22]  71.88 225.55 270 top
C35  SC3D3P50V2CN-GP  [C402H22]  74.8 225.55 270 top
C36  SC3D3P50V2CN-GP  [C402H22]  77.72 225.55 270 top
C37  SC10U10V5KX-2GP  [C805H54]  19.81 222.22 0 top
C38  SC100P50V2JN-3GP  [C402H22]  44.88 231.67 270 top
C41  SC10U10V5KX-2GP  [C805H54]  17.78 222.22 0 top
C42  SCD1U10V2KX-5GP  [C402H22]  13.58 227.2 270 top
C43  SCD1U10V2KX-5GP  [C402H22]  94.67 218.8 90 top
C44  SCD1U10V2KX-5GP  [C402H22]  94.67 217.91 90 top
C45  SCD1U10V2KX-5GP  [C402H22]  94.67 217 90 top
C46  SCD1U10V2KX-5GP  [C402H22]  94.67 216.11 90 top
C47  SCD1U10V2KX-5GP  [C402H22]  94.67 215.15 90 top
C48  SCD1U10V2KX-5GP  [C402H22]  94.67 214.26 90 top
C49  SCD1U10V2KX-5GP  [C402H22]  94.67 213.28 90 top
C50  SCD1U10V2KX-5GP  [C402H22]  94.67 212.37 90 top
C51  SC2D2U10V3KX-1GP  [C603H36]  183.13 222.25 180 top
C53  SCD1U10V2KX-5GP  [C402H22]  114.68 220.09 270 top
C54  SCD1U10V2KX-5GP  [C402H22]  13.49 236.32 270 top
C55  SC100P50V2JN-3GP  [C402H22]  46.94 222.22 180 top
C56  SC10U10V5KX-2GP  [C805H54]  13.77 234.8 270 top
C57  SC10U10V5KX-2GP  [C805H54]  13.77 232.84 270 top
C59  SC22P50V2JN-4GP  [C402H22]  12.45 230 270 top
C60  SC100P50V2JN-3GP  [C402H22]  45.95 216.81 270 top
C64  SC1U6D3V2KX-GP  [C402H22]  191.29 222.45 0 top
C65  SCD1U10V2KX-5GP  [C402H22]  87.12 231.27 0 top
C70  SCD01U25V2KX-3GP  [C402H22]  171.04 157.77 270 top
C71  SCD1U10V2KX-5GP  [C402H22]  170.92 168.31 0 top
C72  SC2D2U10V5KX-3-GP  [C805H58]  170.51 164.39 270 top
C73  SC100P50V2JN-3GP  [C402H22]  44.91 235.51 90 top
C74  SCD1U10V2KX-5GP  [C402H22]  182.7 219.94 0 top
C75  SC1U10V2KX-1GP  [C402H22]  163.53 208.61 180 top
C76  SCD1U16V2ZY-2GP  [C402H22]  185.17 218.39 90 top
C77  SCD1U10V2KX-5GP  [C402H22]  165.25 208.61 180 top
C80  SC100P50V2JN-3GP  [C402H22]  44.88 233.58 90 top
C81  SCD1U10V2KX-5GP  [C402H22]  164.9 211.94 270 top
C82  SC100P50V2JN-3GP  [C402H22]  9.65 212.34 90 top
C83  SCD1U10V2KX-5GP  [C402H22]  164.39 208.61 180 top
C85  SCD1U10V2KX-5GP  [C402H22]  164.9 211.05 270 top
C86  SCD1U10V2KX-5GP  [C402H22]  170.03 212.88 180 top
C88  SC4D7U6D3V3KX-GP  [C603H36]  71.12 158.45 270 top
C89  SCD01U25V2KX-3GP  [C402H22]  181.48 35.89 90 top
C90  SCD1U10V2KX-5GP  [C402H22]  174.5 203.1 0 top
C91  SCD1U10V2KX-5GP  [C402H22]  171.96 202.16 90 top
C92  SC100P50V2JN-3GP  [C402H22]  9.14 207.9 180 top
C93  SCD1U10V2KX-5GP  [C402H22]  174.37 206.07 90 top
C94  SC4D7U10V3KX-GP  [C603H36]  162.76 206.3 270 top
C95  SCD1U16V2KX-3GP  [C402H22]  164.72 206.68 180 top
C96  SCD01U25V2KX-3GP  [C402H22]  174.24 35.33 90 top
C97  SC10P50V2JN-4GP  [C402H22]  176.53 203.45 180 top
C100  SCD1U10V2KX-5GP  [C402H22]  173.43 208.89 180 top
C102  SC100P50V2JN-3GP  [C402H22]  9.65 205.36 90 top
C103  SCD1U25V2KX-2-GP  [C402H22]  179.02 154 270 top
C108  SCD1U25V2KX-2-GP  [C402H22]  186.44 158.52 90 top
C111  SCD1U10V2KX-5GP  [C402H22]  183.57 201.22 180 top
C112  SC10P50V2JN-4GP  [C402H22]  176.53 201.55 0 top
C113  SCD1U25V2KX-2-GP  [C402H22]  184.66 156.49 90 top
C114  SC4D7U10V3KX-GP  [C603H36]  159.61 205.99 180 top
C119  SCD1U10V2KX-4GP  [C402H20]  158.6 205.87 180 top
C120  SCD1U10V2KX-5GP  [C402H22]  165.43 201.85 0 top
C121  SCD1U25V2KX-2-GP  [C402H22]  43.31 198.12 90 top
C122  SCD1U25V2KX-2-GP  [C402H22]  39.37 204.22 180 top
C123  SC10U6D3V5KX-4GP  [C805H58]  124.1 67.94 90 top
C124  SCD1U25V2KX-2-GP  [C402H22]  15.62 204.29 180 top
C125  SCD1U25V2KX-2-GP  [C402H22]  16.64 204.29 180 top
C126  SC470P50V2KX-3GP  [C402H22]  177.39 168.63 90 top
C127  SC10U10V5KX-2GP  [C805H54]  62.76 76.66 90 top
C128  SC4700P50V2KX-1GP  [C402H22]  176.02 165.79 0 top
C129  SC1KP50V2KX-1GP  [C402H22]  183.01 161.95 0 top
C130  SC1KP50V2KX-1GP  [C402H22]  174.09 165.77 180 top
C132  SCD1U10V2KX-5GP  [C402H22]  43.56 190.12 90 top
C133  SCD1U10V2KX-5GP  [C402H22]  43.56 189.23 90 top
C134  SCD1U10V2KX-5GP  [C402H22]  28.7 189.23 0 top
C135  SCD1U10V2KX-5GP  [C402H22]  26.04 189.23 0 top
C136  SC10U10V5KX-2GP  [C805H54]  58.5 82.64 270 top
C137  SCD1U10V2KX-5GP  [C402H22]  11.18 190.63 180 top
C139  SCD1U10V2KX-5GP  [C402H22]  26.92 189.23 0 top
C140  SC180P50V2JN-1GP  [C402H22]  44.32 186.06 0 top
C141  SCD1U10V2KX-5GP  [C402H22]  71.59 156.79 270 top
C142  SCD1U10V2KX-5GP  [C402H22]  29.59 188.34 180 top
C143  SC1U16V3KX-2GP  [C603H36]  108.29 41.03 90 top
C144  SC10U6D3V5KX-4GP  [C805H58]  113.61 50.24 270 top
C145  SCD01U25V2KX-3GP  [C402H22]  181.86 167.54 180 top
C146  SCD1U25V2KX-2-GP  [C402H22]  43.31 196.34 90 top
C148  SCD22U10V2KX-1GP  [C402H22]  23.44 182.19 270 top
C149  SCD22U10V2KX-1GP  [C402H22]  23.44 181.31 270 top
C151  SC4D7U6D3V3KX-GP  [C603H36]  72.77 45.47 0 top
C152  SCD1U25V2KX-2-GP  [C402H22]  73.89 45.57 0 top
C153  SC47P50V2JN-3GP  [C402H22]  169.09 162.97 270 top
C157  SCD1U25V2KX-2-GP  [C402H22]  179.02 154.89 90 top
C158  SCD22U10V2KX-1GP  [C402H22]  23.75 179.07 270 top
C159  SCD1U10V2KX-5GP  [C402H22]  44.51 183.07 90 top
C160  SCD1U10V2KX-5GP  [C402H22]  44.51 182.18 90 top
C162  SCD22U10V2KX-1GP  [C402H22]  23.75 178.05 270 top
C164  SCD1U25V2KX-2-GP  [C402H22]  184 158.02 180 top
C165  SCD22U10V2KX-1GP  [C402H22]  23.75 175.01 270 top
C167  SCD22U10V2KX-1GP  [C402H22]  23.75 173.99 270 top
C169  SCD1U25V2KX-2-GP  [C402H22]  181.74 155.45 90 top
C172  SCD1U10V2KX-5GP  [C402H22]  171.58 155.22 0 top
C173  SCD22U10V2KX-1GP  [C402H22]  23.75 171.07 270 top
C174  SC470P50V2KX-3GP  [C402H22]  183.8 167.54 180 top
C175  SCD22U10V2KX-1GP  [C402H22]  23.75 170.05 270 top
C176  SC2200P50V2KX-2GP  [C402H22]  178.82 168.14 0 top
C177  SC1U16V3KX-5GP  [C603H36]  83.29 196.7 180 top
C179  SC10U16V6KX-2GP  [C1206H71]  162.05 197.23 180 top
C180  SC1U16V3KX-5GP  [C603H36]  141.6 196.55 90 top
C181  SC10U16V6KX-2GP  [C1206H71]  116.76 207.42 180 top
C183  SC1U16V5KX-3GP  [C805H54]  132.61 206.53 180 top
C184  SCD1U25V2KX-2-GP  [C402H22]  38.48 204.22 180 top
C185  SC47P50V2JN-3GP  [C402H22]  185.65 164.76 90 top
C186  SC1U16V5KX-3GP  [C805H54]  91.14 203.45 270 top
C187  SC4D7U6D3V3KX-GP  [C603H36]  155.7 154.81 270 top
C188  SCD22U10V2KX-1GP  [C402H22]  23.75 167.34 270 top
C191  SCD1U10V2KX-4GP  [C402H20]  7.49 185.93 90 top
C193  SCD22U10V2KX-1GP  [C402H22]  23.75 166.32 270 top
C194  SCD015U25V2KX-GP  [C402H22]  73.91 39.12 90 top
C195  SC1U16V2KX-GP  [C402H22]  69.7 40.77 180 top
C198  SC1U16V3KX-2GP  [C603H36]  69.16 79.04 0 top
C199  SC3300P50V2KX-1GP  [C402H22]  74.12 35.43 270 top
C200  SC10U16V6KX-2GP  [C1206H71]  91.03 205.51 270 top
C201  SCD1U25V3KX-GP  [C603H36]  188.04 175.03 270 top
C202  SCD1U10V2KX-5GP  [C402H22]  124 69.42 90 top
C204  SCD1U25V3KX-GP  [C603H36]  90.27 199.42 0 top
C205  SCD1U10V2KX-5GP  [C402H22]  57.94 80.12 270 top
C207  SCD22U10V2KX-1GP  [C402H22]  24.26 161.04 270 top
C208  SC150P50V2JN-3GP  [C402H22]  73.91 38.23 270 top
C209  SCD022U16V2KX-3GP  [C402H22]  69.09 42.16 270 top
C210  SCD22U10V2KX-1GP  [C402H22]  24.26 160.02 270 top
C213  SC4D7U6D3V3KX-GP  [C603H36]  66.42 41.27 0 top
C216  SCD22U10V2KX-1GP  [C402H22]  23.75 157.1 270 top
C227  SCD1U25V2KX-2-GP  [C402H22]  176.58 154.37 0 top
C229  SC1U10V3KX-4GP-U  [C603H36]  169.49 159.51 180 top
C230  SCD22U10V2KX-1GP  [C402H22]  23.75 156.08 270 top
C231  SCD1U10V2KX-5GP  [C402H22]  44.7 143.38 0 top
C232  SC1U16V3KX-2GP  [C603H36]  173.15 196.9 180 top
C233  SC22P50V2JN-4GP  [C402H22]  178.36 166.7 90 top
C234  SC2200P50V2KX-2GP  [C402H22]  185.65 165.77 90 top
C235  SC2K2P50V3KX-GP  [C603]  181 179.46 90 top
C236  SC2K2P50V3KX-GP  [C603]  91.69 190.37 270 top
C237  SC1U16V3KX-5GP  [C603H36]  186.13 182.52 90 top
C239  SC2K2P50V3KX-GP  [C603]  136.73 192.3 90 top
C240  SCD1U10V2KX-5GP  [C402H22]  44.7 155.19 0 top
C241  SCD1U25V3KX-GP  [C603H36]  143.97 189.79 270 top
C244  SCD22U10V2KX-1GP  [C402H22]  23.75 153.03 270 top
C252  SCD1U16V2KX-3GP  [C402H22]  108 33.83 90 top
C253  SC1U16V5KX-3GP  [C805H54]  168.28 196.72 180 top
C254  SCD1U10V2KX-5GP  [C402H22]  60.18 68.64 180 top
C255  SCD22U10V2KX-1GP  [C402H22]  23.75 152.02 270 top
C265  SCD22U10V2KX-1GP  [C402H22]  23.77 148.89 270 top
C266  SCD1U10V2KX-5GP  [C402H22]  44.7 145.8 0 top
C267  SCD1U10V2KX-5GP  [C402H22]  44.2 166.37 180 top
C269  SCD22U10V2KX-1GP  [C402H22]  23.77 147.88 270 top
C270  SC22U6D3V5MX-2GP  [C805H58]  102.8 184.03 270 top
C271  SC22U6D3V5MX-2GP  [C805H58]  161.56 170.93 0 top
C279  SCD22U10V2KX-1GP  [C402H22]  23.75 143 270 top
C280  SCD22U10V2KX-1GP  [C402H22]  23.75 141.99 270 top
C281  SCD22U10V2KX-1GP  [C402H22]  23.75 139.06 270 top
C284  SCD22U10V2KX-1GP  [C402H22]  23.75 138.05 270 top
C290  SCD22U10V2KX-1GP  [C402H22]  23.75 135 270 top
C291  SCD22U10V2KX-1GP  [C402H22]  23.75 133.99 270 top
C292  SCD22U10V2KX-1GP  [C402H22]  23.75 130.05 270 top
C294  SCD22U10V2KX-1GP  [C402H22]  23.75 131.06 270 top
C295  SCD22U10V2KX-1GP  [C402H22]  23.75 127 270 top
C296  SCD22U10V2KX-1GP  [C402H22]  23.75 125.98 270 top
C297  SCD22U10V2KX-1GP  [C402H22]  23.75 123.06 270 top
C299  SCD22U10V2KX-1GP  [C402H22]  23.75 122.05 270 top
C300  SCD22U10V2KX-1GP  [C402H22]  23.73 117.95 270 top
C301  SCD22U10V2KX-1GP  [C402H22]  23.73 119.07 270 top
C304  SC1U16V5KX-3GP  [C805H54]  189.08 110.24 0 top
C306  SC2D2U10V3KX-1GP  [C603H36]  5.52 113.86 270 top
C308  SCD1U10V2KX-5GP  [C402H22]  5.67 115.97 270 top
C310  SC2D2U10V3KX-1GP  [C603H36]  9.14 109.37 90 top
C315  SCD1U10V2KX-5GP  [C402H22]  9.45 108.33 90 top
C350  SC22U6D3V5MX-2GP  [C805H58]  117.6 149.46 0 top
C352  SC10U10V5KX-2GP  [C805H54]  60.73 33.01 0 top
C353  SC10U10V5KX-2GP  [C805H54]  24.26 67.94 270 top
C354  SCD01U25V2KX-3GP  [C402H22]  25.91 70.54 90 top
C355  SCD1U10V2KX-5GP  [C402H22]  24.82 61.01 90 top
C357  SCD01U25V2KX-3GP  [C402H22]  75.31 70.99 270 top
C358  SCD01U25V2KX-3GP  [C402H22]  75.31 70.1 270 top
C359  SCD01U25V2KX-3GP  [C402H22]  75.31 69.22 270 top
C360  SCD01U25V2KX-3GP  [C402H22]  75.31 68.33 270 top
C361  SCD01U25V2KX-3GP  [C402H22]  96.98 70.36 0 top
C362  SCD01U25V2KX-3GP  [C402H22]  97.87 70.36 0 top
C363  SCD01U25V2KX-3GP  [C402H22]  100.81 70.36 0 top
C364  SCD01U25V2KX-3GP  [C402H22]  101.7 70.36 0 top
C366  SCD1U10V2KX-5GP  [C402H22]  24.82 61.9 90 top
C368  SCD1U10V2KX-5GP  [C402H22]  48.78 35.05 180 top
C369  SCD1U10V2KX-5GP  [C402H22]  49.66 35.06 180 top
C370  SC1U6D3V2KX-GP  [C402H22]  50.55 35.43 180 top
C373  SCD1U16V2ZY-2GP  [C402H22]  176.29 68.96 270 top
C374  SCD1U16V2ZY-2GP  [C402H22]  178.19 68.96 90 top
C375  SCD1U16V2ZY-2GP  [C402H22]  164.39 67.51 90 top
C376  SCD1U10V2KX-5GP  [C402H22]  44.7 153.29 0 top
C377  SC10U10V5KX-2GP  [C805H54]  41.62 138.49 90 top
C378  SC12P50V2JN-3GP  [C402H24]  41.55 69.97 180 top
C379  SC12P50V2JN-3GP  [C402H24]  41.55 65.26 0 top
C380  SCD1U16V2ZY-2GP  [C402H22]  172.7 73.25 0 top
C381  SC1U16V3KX-2GP  [C603H36]  93.24 56.95 0 top
C382  SCD1U16V2KX-3GP  [C402H22]  100.56 49.58 90 top
C383  SCD47U10V2KX-GP  [C402H22]  191.29 224.38 0 top
C385  SCD1U16V2KX-3GP  [C402H22]  98.27 63.53 180 top
C386  SCD1U16V2KX-3GP  [C402H22]  98.37 51.61 0 top
C387  SC22U6D3V5MX-2GP  [C805H58]  119.53 149.46 0 top
C388  SCD1U10V2KX-5GP  [C402H22]  170.41 72.84 90 top
C389  SC4D7U6D3V3KX-GP  [C603H36]  97.23 63.91 180 top
C390  SC1KP50V2KX-1GP  [C402H22]  178.19 71.08 270 top
C391  SC22U6D3V5MX-2GP  [C805H58]  121.67 149.48 0 top
C392  SCD1U16V2ZY-2GP  [C402H22]  162.48 67.51 270 top
C393  SCD1U16V2ZY-2GP  [C402H22]  160.55 67.51 90 top
C394  SC1U6D3V2KX-GP  [C402H22]  15.16 63.6 0 top
C395  SC1U6D3V2KX-GP  [C402H22]  16.05 63.6 0 top
C396  SC1U6D3V2KX-GP  [C402H22]  16.97 63.6 0 top
C397  SC22U6D3V5MX-2GP  [C805H58]  102.78 182 270 top
C398  SCD1U10V2KX-5GP  [C402H22]  46.99 61.67 270 top
C399  SCD1U10V2KX-5GP  [C402H22]  185.29 65.66 180 top
C400  SCD1U16V2KX-3GP  [C402H22]  104.11 65.56 180 top
C401  SCD1U10V2KX-5GP  [C402H22]  121.93 211.51 90 top
C402  SCD1U16V2KX-3GP  [C402H22]  101.04 51.56 0 top
C403  SCD1U10V2KX-5GP  [C402H22]  129.11 213.46 180 top
C404  SCD1U16V2ZY-2GP  [C402H22]  158.65 67.51 270 top
C405  SCD1U10V2KX-5GP  [C402H22]  165.1 214.48 270 top
C406  SCD1U10V2KX-5GP  [C402H22]  165.1 213.59 270 top
C407  SCD1U25V2KX-2-GP  [C402H22]  184.81 61.98 270 top
C408  SCD1U25V2KX-2-GP  [C402H22]  183.64 22.35 180 top
C410  SCD1U10V2KX-5GP  [C402H22]  170.38 69.67 90 top
C411  SC1U6D3V2KX-GP  [C402H22]  17.88 63.6 0 top
C412  SCD1U10V2KX-5GP  [C402H22]  10.41 33.02 0 top
C414  SC1U10V2KX-1GP  [C402H22]  185.42 49.53 0 top
C415  SCD1U10V2KX-5GP  [C402H22]  20.28 37.48 270 top
C417  SCD1U10V2KX-5GP  [C402H22]  11.81 36.58 270 top
C418  SCD1U10V2KX-5GP  [C402H22]  44.2 168.28 180 top
C420  SC1U6D3V2KX-GP  [C402H22]  117.7 26.12 0 top
C421  SCD1U10V2KX-5GP  [C402H22]  29.32 149.05 0 top
C422  SC1U6D3V2KX-GP  [C402H22]  116.28 27.66 270 top
C423  SC12P50V3JN-GP  [C603H36]  21.34 23.01 0 top
C424  SCD1U10V2KX-5GP  [C402H22]  30.2 149.05 0 top
C429  SC10U10V5KX-2GP  [C805H54]  177.29 10.79 0 top
C430  SCD1U10V2KX-5GP  [C402H22]  148.5 65.24 180 top
C431  SCD1U10V2KX-5GP  [C402H22]  149.41 65.24 180 top
C433  SC1U6D3V2KX-GP  [C402H22]  18.8 63.6 0 top
C434  SCD1U16V2ZY-2GP  [C402H22]  19.68 63.6 0 top
C435  SCD1U10V2KX-5GP  [C402H22]  173.3 23.95 90 top
C436  SC1U6D3V2KX-GP  [C402H22]  12.83 30.86 270 top
C438  SC1U10V2KX-1GP  [C402H22]  184.72 38.86 270 top
C440  SC10U10V5KX-2GP  [C805H54]  158.85 24.13 270 top
C441  SCD1U10V2KX-5GP  [C402H22]  181.91 25.1 0 top
C443  SC15P50V3JN-GP  [C603H36]  21.34 25.7 180 top
C445  SC1U6D3V2KX-GP  [C402H22]  57.15 39.5 180 top
C446  SC1U6D3V2KX-GP  [C402H22]  50.77 31.5 0 top
C447  SC1U6D3V2KX-GP  [C402H22]  14.73 31.8 90 top
C451  SC1U6D3V2KX-GP  [C402H22]  66.32 35.71 90 top
C452  SCD1U10V2KX-5GP  [C402H22]  121.93 212.42 90 top
C453  SCD1U10V2KX-5GP  [C402H22]  128.24 213.46 180 top
C456  SCD1U10V2KX-5GP  [C402H22]  184.56 26.24 270 top
C460  SC2D2U10V3KX-1GP  [C603H36]  90.04 10.41 270 top
C461  SCD1U10V2KX-5GP  [C402H22]  90.42 11.43 270 top
C462  SCD1U10V2KX-5GP  [C402H22]  90.42 12.32 270 top
C463  SC1U6D3V2KX-GP  [C402H22]  42.67 26.16 0 top
C466  SC1U6D3V2KX-GP  [C402H22]  56.26 39.5 180 top
C467  SC10U10V3MX-GP  [C603H36]  71.07 60.76 0 top
C469  SC10U10V5KX-2GP  [C805H54]  58.78 33.02 0 top
C470  SC1U6D3V2KX-GP  [C402H22]  74.3 30.58 90 top
C472  SC1U6D3V2KX-GP  [C402H22]  31.06 14.88 270 top
C475  SC10U10V5KX-2GP  [C805H54]  104.14 24.77 180 top
C477  SC10U10V3MX-GP  [C603H36]  69.88 60.76 0 top
C478  SCD1U10V2KX-5GP  [C402H22]  104.14 22.48 90 top
C479  SCD1U16V2ZY-2GP  [C402H22]  12.7 12.95 0 top
C481  SCD1U10V2KX-5GP  [C402H22]  105.66 22.99 180 top
C482  SCD1U10V2KX-5GP  [C402H22]  107.7 22.99 180 top
C483  SC1U10V2KX-1GP  [C402H22]  101.35 5.46 0 top
C484  SC1U10V3KX-3GP  [C603H36]  90.04 9.22 270 top
C486  SCD1U10V2KX-5GP  [C402H22]  109.73 22.99 180 top
C489  SCD1U10V2KX-5GP  [C402H22]  105.33 80.29 0 top
C490  SCD1U10V2KX-5GP  [C402H22]  109.98 20.65 90 top
C491  SC10U10V5KX-2GP  [C805H54]  59.69 40.39 180 top
C493  SC1U6D3V2KX-GP  [C402H22]  109.98 16.76 90 top
C494  SCD1U10V2KX-5GP  [C402H22]  109.98 19.76 90 top
C496  SCD1U16V2ZY-2GP  [C402H22]  12.7 11.05 0 top
C497  SC2200P50V2KX-2GP  [C402H22]  82.22 193.65 0 top
C498  SC2200P50V2KX-2GP  [C402H22]  53.75 41.48 90 top
C499  SCD1U10V2KX-5GP  [C402H22]  122.58 84.7 270 top
C500  SC22U6D3V5MX-2GP  [C805H58]  163.61 170.91 0 top
C501  SC22U6D3V5MX-2GP  [C805H58]  113.48 149.45 0 top
C502  SC22U6D3V5MX-2GP  [C805H58]  115.41 149.45 0 top
C503  SC22U6D3V5MX-2GP  [C805H58]  123.78 149.46 0 top
C504  SC22U6D3V5MX-2GP  [C805H58]  111.41 145.89 180 top
C505  SCD1U10V2KX-5GP  [C402H22]  134.62 43.18 180 top
C506  SC1U6D3V2KX-GP  [C402H22]  34.09 62.56 180 top
C512  SCD1U16V2ZY-2GP  [C402H22]  171.44 122.77 180 top
C516  SC100P50V2JN-3GP  [C402H22]  106.05 6.17 270 top
C518  SC10U10V3MX-GP  [C603H36]  58.91 62.1 0 top
C520  SCD1U10V2KX-4GP  [C402H20]  131.19 84.71 90 top
C521  SC22U6D3V5MX-2GP  [C805H58]  109.39 149.45 0 top
C522  SC22U6D3V5MX-2GP  [C805H58]  113.52 145.89 180 top
C523  SC1U10V2KX-1GP  [C402H22]  69.07 64.42 180 top
C524  SC1U6D3V2KX-GP  [C402H22]  11.3 33.02 0 top
C525  SCD1U10V2KX-5GP  [C402H22]  20.29 33.78 270 top
C526  SCD1U10V2KX-5GP  [C402H22]  19.94 45.72 180 top
C527  SC1U6D3V2KX-GP  [C402H22]  62.48 29.59 90 top
C528  SCD1U10V2KX-5GP  [C402H22]  163.75 15.98 90 top
C529  SC1U6D3V2KX-GP  [C402H22]  162.31 18.29 0 top
C536  SC10U10V3MX-GP  [C603H36]  60.13 62.1 0 top
C537  SC22U6D3V5MX-2GP  [C805H58]  109.32 153.09 0 top
C538  SCD1U10V2KX-5GP  [C402H22]  32.99 134.49 0 top
C539  SCD1U10V2KX-5GP  [C402H22]  33.91 134.49 0 top
C540  SCD1U16V2ZY-2GP  [C402H22]  42.8 61.59 180 top
C541  SCD1U10V2KX-5GP  [C402H22]  44.83 61.59 180 top
C542  SC22U6D3V5MX-2GP  [C805H58]  111.36 153.12 0 top
C544  SC10U10V5KX-2GP  [C805H54]  31.45 66.66 270 top
C545  SC1U6D3V2KX-GP  [C402H22]  33.6 65.25 90 top
C546  SC22U6D3V5MX-2GP  [C805H58]  113.39 153.09 0 top
C547  SC22U6D3V5MX-2GP  [C805H58]  115.45 153.09 0 top
C548  SC22U6D3V5MX-2GP  [C805H58]  115.46 145.89 180 top
C549  SC22U6D3V5MX-2GP  [C805H58]  117.58 153.09 0 top
C550  SC22U6D3V5MX-2GP  [C805H58]  119.56 153.09 0 top
C551  SC22U6D3V5MX-2GP  [C805H58]  117.48 145.88 180 top
C552  SC22U6D3V5MX-2GP  [C805H58]  121.57 153.09 0 top
C556  SC1U6D3V2KX-GP  [C402H22]  62.13 33.25 0 top
C557  SC1U6D3V2KX-GP  [C402H22]  35.81 28.83 0 top
C558  SC22U6D3V5MX-2GP  [C805H58]  123.7 153.09 0 top
C560  SC22U6D3V5MX-2GP  [C805H58]  119.46 145.89 180 top
C561  SC22U6D3V5MX-2GP  [C805H58]  107.23 149.46 0 top
C562  SC22U6D3V5MX-2GP  [C805H58]  121.6 145.89 180 top
C563  SC22U6D3V5MX-2GP  [C805H58]  123.63 145.89 180 top
C564  SC22U6D3V5MX-2GP  [C805H58]  107.27 153.09 0 top
C565  SC1U6D3V2KX-GP  [C402H22]  63.94 33.24 0 top
C566  SC1U6D3V2KX-GP  [C402H22]  63.04 33.25 0 top
C567  SCD1U16V2ZY-2GP  [C402H22]  155.37 153.8 90 top
C568  SCD1U16V2ZY-2GP  [C402H22]  49.33 36.88 270 top
C569  SCD1U10V2KX-5GP  [C402H22]  23.62 33.02 90 top
C570  SC22U6D3V5MX-2GP  [C805H58]  109.38 145.89 180 top
C571  SC1U6D3V2KX-GP  [C402H22]  57.33 33.2 0 top
C572  SC1U6D3V2KX-GP  [C402H22]  42.21 29.41 0 top
C573  SC22U6D3V5MX-2GP  [C805H58]  111.33 149.45 0 top
C574  SC22U6D3V5MX-2GP  [C805H58]  107.35 145.89 180 top
C575  SCD1U16V2ZY-2GP  [C402H22]  55.63 17.74 180 top
C576  SCD1U10V2KX-5GP  [C402H22]  176.66 141.16 270 top
C577  SCD1U10V2KX-5GP  [C402H22]  105.45 103.3 180 top
C578  SCD1U10V2KX-5GP  [C402H22]  111.06 103.28 180 top
C579  SC4D7U6D3V3KX-GP  [C603H36]  52.39 104.18 180 top
C580  SCD1U10V2KX-5GP  [C402H22]  175.26 83.69 270 top
C581  SCD1U10V2KX-4GP  [C402H20]  173.1 82.68 90 top
C582  SCD1U10V2KX-5GP  [C402H22]  117.03 103.38 180 top
C583  SC22U6D3V5MX-2GP  [C805H58]  91.13 82.88 270 top
C584  SC22U6D3V5MX-2GP  [C805H58]  91.13 80.85 270 top
C585  SC22U6D3V5MX-2GP  [C805H58]  127.38 82.5 90 top
C586  SC22U6D3V5MX-2GP  [C805H58]  127.38 84.43 90 top
C587  SCD1U10V2KX-5GP  [C402H22]  51.3 104.26 180 top
C588  SCD1U10V2KX-4GP  [C402H20]  99.31 80.39 0 top
C589  SCD1U10V2KX-5GP  [C402H22]  118.62 84.71 270 top
C590  SCD1U10V2KX-4GP  [C402H20]  171.07 82.68 270 top
C591  SCD1U10V2KX-5GP  [C402H22]  169.04 83.57 90 top
C592  SCD1U10V2KX-5GP  [C402H22]  177.16 84.84 90 top
C593  SCD1U10V2KX-5GP  [C402H22]  112.52 84.71 90 top
C594  SCD1U16V2ZY-2GP  [C402H22]  116.59 84.71 90 top
C595  SC1U6D3V2KX-GP  [C402H22]  98.42 80.39 0 top
C596  SCD1U10V2KX-5GP  [C402H22]  108.46 84.71 90 top
C597  SCD1U10V2KX-5GP  [C402H22]  98.93 84.71 90 top
C598  SCD1U16V2ZY-2GP  [C402H22]  100.97 84.71 270 top
C599  SCD1U10V2KX-5GP  [C402H22]  94.87 84.71 90 top
C600  SCD1U16V2ZY-2GP  [C402H22]  96.9 84.71 270 top
C601  SCD1U10V2KX-5GP  [C402H22]  103 84.71 90 top
C602  SCD1U16V2ZY-2GP  [C402H22]  105.03 84.71 270 top
C603  SC1U6D3V2KX-GP  [C402H22]  95.76 80.39 0 top
C604  SC1U6D3V2KX-GP  [C402H22]  96.65 80.39 0 top
C605  SC1U6D3V2KX-GP  [C402H22]  94.87 80.39 0 top
C606  SC1U6D3V2KX-GP  [C402H22]  97.54 80.39 0 top
C607  SCD1U10V2KX-5GP  [C402H22]  106.22 80.29 0 top
C608  SCD1U16V2ZY-2GP  [C402H22]  114.55 84.71 270 top
C609  SCD1U16V2ZY-2GP  [C402H22]  110.49 84.71 270 top
C610  SCD1U10V2KX-5GP  [C402H22]  55.04 82.58 180 top
C611  SC1U6D3V2KX-GP  [C402H22]  93.98 80.39 0 top
C612  SC4D7U6D3V3KX-GP  [C603H36]  56.11 82.35 180 top
C613  SCD1U16V2ZY-2GP  [C402H22]  120.58 84.7 90 top
C614  SCD1U10V2KX-5GP  [C402H22]  66.32 36.63 90 top
C615  SCD1U10V2KX-5GP  [C402H22]  38.48 27.18 0 top
C616  SCD1U10V2KX-5GP  [C402H22]  167.13 84.58 270 top
C678  SCD01U25V2KX-3GP  [C402H22]  4.57 107.29 0 top
C680  SC1U10V2KX-1GP  [C402H22]  6.93 104.83 90 top
C1669  SC1U6D3V2KX-GP  [C402H22]  82.17 27.1 270 top
C1671  SC1U6D3V2KX-GP  [C402H22]  94.49 28.35 90 top
C1672  SC1U10V2KX-1GP  [C402H22]  61.97 15.79 0 top
C1673  SC1U6D3V2KX-GP  [C402H22]  28.68 66.04 90 top
C3310  SCD022U16V2KX-3GP  [C402H22]  177.16 82.8 270 top
C3311  SCD022U16V2KX-3GP  [C402H22]  164.41 84.25 270 top
C3312  SCD022U16V2KX-3GP  [C402H22]  171.96 121.28 270 top
C3315  SCD1U10V2KX-4GP  [C402H20]  30.86 27.69 180 top
C3316  SC22P50V2JN-4GP  [C402H22]  13 62.33 90 top
C3317  SC22P50V2JN-4GP  [C402H22]  13 63.37 90 top
C3318  SC22P50V2JN-4GP  [C402H22]  13 61.29 90 top
C3319  SC22P50V2JN-4GP  [C402H22]  13 58.17 90 top
C3320  SC1U10V2KX-1GP  [C402H22]  140.16 42.39 180 top
C3321  SC1U16V2KX-GP  [C402H22]  193.88 220.47 0 top
C3322  SC22P50V2JN-4GP  [C402H22]  13 60.25 90 top
C3323  SC22P50V2JN-4GP  [C402H22]  13 59.21 90 top
C3324  SC4D7U6D3V3KX-GP  [C603H36]  104.29 80.29 0 top
C3325  SCD1U10V2KX-5GP  [C402H22]  167.21 216.61 90 top
C3326  SCD1U10V2KX-5GP  [C402H22]  167.21 215.75 90 top
C3327  SCD1U10V2KX-5GP  [C402H22]  167.21 214.88 90 top
CMCLR1  PIN-CON3-S-GP  [21S-91-03GB01]  117.86 30.59 180 top
D1  BAT54A-12-GP  [SOT23-2D4-312H44]  35.43 224.92 0 top
D2  AZ2015-01H-GP  [SOD523AKH28]  16.13 237.62 90 top
D8  1SS355-4-GP  [SOD323AKH38]  89.03 225.81 180 top
D18  1SS355-4-GP  [SOD323AKH38]  114.68 217.3 180 top
D21  1N4148WS-7-F-GP  [SOD323AKH42]  187 104.22 180 top
D23  BAS40-05-7-F-1-GP  [SOT23-2D4-312H48]  142.85 38.81 0 top
D26  BAS40-05-7-F-1-GP  [SOT23-2D4-312H48]  142.85 34.72 180 top
D37  1N4148WS-7-F-GP  [SOD323AKH42]  187.07 109.7 180 top
DB1  CLX-CON2-S3-GP  [G800W306018EU]  99.03 30.56 0 top
DIMM1  DDR3-240P-4-GP  [78079-0001]  124.54 97.8 180 top
DIMM2  DDR3-240P-4-GP  [78079-0001]  124.54 89.9 180 top
DQ61  MMBT3904-4-GP  [SOT23CBE2D4H44]  159.74 14.55 270 top
F5  POLYSW-2A8V-1-GP-U  [POLYSW-4633-UH24]  141.12 214.91 270 top
F6  POLYSW-1D5A8V-3-GP  [POLYSW-3217-UH40]  147.19 215.65 270 top
F7  POLYSW-1D5A8V-3-GP  [POLYSW-3217-UH40]  91.95 223.49 0 top
F8  POLYSW-2A8V-1-GP-U  [POLYSW-4633-UH24]  148.77 59.33 270 top
F9  POLYSW-1D5A8V-3-GP  [POLYSW-3217-UH40]  167.82 71.09 0 top
F17  POLYSW-1D5A8V-3-GP  [POLYSW-3217-UH40]  119.63 221.87 0 top
F18  POLYSW-1D5A8V-3-GP  [POLYSW-3217-UH40]  189.87 230.5 90 top
FL1  MCB1005S121FBP-GP  [L402H24]  44.91 234.54 90 top
FL2  MCB1005S121FBP-GP  [L402H24]  44.88 232.64 90 top
FL3  MCB1005S121FBP-GP  [L402H24]  11.18 207.9 0 top
FL4  MCB1005S121FBP-GP  [L402H24]  9.65 206.38 270 top
FL5  MCB1005S121FBP-GP  [L402H24]  9.65 211.33 90 top
FNCPU1  TYCO-CON4-S3-GP  [HF08040-M1]  194.45 110.44 90 top
FVS1  TPAD385X385-GP  [TPAD385X385]  14.68 72.82 0 top
G1  COPPER-CLOSE-GP-U  [CON2C-U]  170.73 178.6 225 bottom
G2  COPPER-CLOSE-GP-U  [CON2C-U]  169.32 177.18 225 bottom
G3  -  [GAP-CLOSE-PWR]  106.68 25.65 90 top
G4  -  [GAP-CLOSE-PWR]  108.71 25.65 90 top
G5  -  [GAP-CLOSE-PWR]  114.17 22.23 0 top
G6  -  [GAP-CLOSE-PWR]  113.41 17.65 270 top
G7  -  [GAP-CLOSE-PWR]  105.66 25.65 270 top
G8  COPPER-CLOSE-GP-U  [CON2C-U]  107.19 194.18 315 bottom
G9  COPPER-CLOSE-GP-U  [CON2C-U]  108.58 192.79 315 bottom
G10  COPPER-CLOSE-GP-U  [CON2C-U]  119.45 196.52 45 bottom
G11  COPPER-CLOSE-GP-U  [CON2C-U]  118.11 195.17 45 bottom
H1  GENS315R158-8-F-A-GP  [GENS315R158-8-F-A]  36.17 233.84 0 top
H2  GENS315R158-8-F-A-GP  [GENS315R158-8-F-A]  193.65 6.51 0 top
H3  GENS315R158-8-F-A-GP  [GENS315R158-8-F-A]  36.17 6.51 0 top
H4  GENS315R158-8-F-A-GP  [GENS315R158-8-F-A]  193.65 210.98 0 top
H5  GENS315R158-8-F-A-GP  [GENS315R158-8-F-A]  193.65 78.9 0 top
H6  GENS315R158-8-F-A-GP  [GENS315R158-8-F-A]  36.17 78.9 0 top
H7  STF256R107H132-1-GP  [STF256R107H132]  61.66 144.05 0 top
HDMI1  SKT-HDMI19P-57-GP  [G3168-18000101-00]  110.83 234.45 180 top
L1  MCB1005S121FBP-GP  [L402H24]  9.3 215.37 270 top
L2  MCB1005S121FBP-GP  [L402H24]  11.18 209.8 0 top
L3  -  [0R0805-PAD]  118.06 227.03 0 top
L4  MLB-201209-8-GP  [L201209H44]  91.95 229.11 0 top
L5  FCM1608CF-750T2-GP  [L1608-UH38]  77.34 228.73 90 top
L6  FCM1608CF-750T2-GP  [L1608-UH38]  71.5 228.73 90 top
L7  FCM1608CF-750T2-GP  [L1608-UH38]  74.42 228.73 90 top
L8  MHC1608S800QBP-GP  [L603H38]  16.31 238.86 270 top
L11  FCM1608CF-750T2-GP  [L1608-UH38]  71.5 226.57 270 top
L12  FCM1608CF-750T2-GP  [L1608-UH38]  74.42 226.57 270 top
L13  FCM1608CF-750T2-GP  [L1608-UH38]  77.34 226.57 270 top
L14  MCB1005S121FBP-GP  [L402H24]  43.56 224.36 270 top
L15  MCB1005S121FBP-GP  [L402H24]  44.88 230.71 90 top
L16  MCB1005S121FBP-GP  [L402H24]  45.97 222.2 0 top
L17  FCM1608CF-750T2-GP  [L1608-UH38]  79.38 226.19 180 top
L18  FILTER-4P-113-GP  [L125100-4P-3H27]  124.08 215.14 0 top
L19  FILTER-4P-113-GP  [L125100-4P-3H27]  121.72 215.11 0 top
L20  FCM1608CF-750T2-GP  [L1608-UH38]  81.41 226.19 180 top
L21  MCB1005S121FBP-GP  [L402H24]  47.45 216.31 180 top
L22  FILTER-4P-113-GP  [L125100-4P-3H27]  127.91 217.88 0 top
L23  IND-4D7UH-210-GP  [L3330-1230H95]  162.56 203.58 270 top
L24  FILTER-4P-113-GP  [L125100-4P-3H27]  129.97 217.88 0 top
L27  COIL-D36UH-10-GP-U  [RT-D6-4D5-1010H375]  168 180.59 0 top
L32  FILTER-4P-113-GP  [L125100-4P-3H27]  149.05 69.72 0 top
L39  COIL-D36UH-10-GP-U  [RT-D6-4D5-1010H375]  105.45 191.67 90 top
L40  COIL-D36UH-10-GP-U  [RT-D6-4D5-1010H375]  120.83 192.91 0 top
L44  MCB1608S601FBP-GP  [L603H38]  24.26 71.12 0 top
L45  COIL-1UH-64-GP  [RT-D6D5-13H414-U]  126.95 35.51 0 top
L50  COIL-1D2UH-35-GP  [RT-D6D2-108108H426]  115.57 64.01 270 top
L51  FILTER-4P-113-GP  [L125100-4P-3H27]  146.61 69.72 0 top
LED1  LED-Y-11-GP  [19-21UBC-1]  181.09 22.23 180 top
LEDH1  DVD-CONN12A-FP2GP  [14452190]  8 17 270 top
LPC1  JWT-CONN14A-S3-GP  [A2005WV0-2DX7P-6T-2D3]  20 6.27 180 top
MECLR1  PIN-CON3-S-GP  [21S-91-03GB01]  5.34 72.14 270 top
MINI1  MINIPCI52P-6-GP  [80051-6021]  37.66 156.15 270 top
NOREF  -  [unnamed]  53.26 35.03 0 top
NOREF#2  -  [#2]  0 0 0 top
NOREF#3  -  [unnamed]  195 239 0 top
NOREF#4  -  [unnamed]  77.38 112 0 top
NOREF#5  -  [unnamed]  77.38 187 0 top
NOREF#6  -  [#2]  162.42 121.62 0 top
NOREF#7  -  [unnamed]  9.4 239.27 0 top
NOREF#8  -  [unnamed]  5 5 0 top
NOREF#9  -  [#2]  0 0 0 top
NOREF#10  -  [#2]  41.68 105.11 0 top
NOREF#11  -  [unnamed]  189.61 13.97 0 top
NOREF#12  -  [unnamed]  152.39 112 0 top
NOREF#13  -  [#2]  59.36 110.44 0 top
NOREF#14  -  [#2]  0 0 0 top
NOREF#15  -  [unnamed]  5 239 0 top
NOREF#16  -  [#2]  53.09 156.13 90 top
NOREF#17  -  [unnamed]  159.13 186.94 0 top
NOREF#18  -  [unnamed]  16.26 59.03 0 top
NOREF#19  -  [unnamed]  152.39 187 0 top
NOREF#20  -  [unnamed]  194.01 233.53 0 top
NOREF#21  -  [unnamed]  9.4 239.27 180 bottom
NOREF#22  -  [unnamed]  189.61 13.97 180 bottom
NOREF#23  -  [unnamed]  194.01 233.53 180 bottom
PC63  SC22P50V2JN-4GP  [C402H22]  129.75 41.34 270 top
PC65  SC1U16V3KX-2GP  [C603H36]  130.4 52.88 90 top
PC69  SCD1U25V3KX-GP  [C603H36]  125.07 51.16 90 top
PC72  SC1U16V3KX-2GP  [C603H36]  124.89 45.9 180 top
PC73  SC1500P50V3KX-GP  [C603]  127.74 56.18 90 top
PC78  SC100P50V2JN-3GP  [C402H22]  60.25 64.81 180 top
PC352  SCD1U10V2KX-5GP  [C402H22]  67.59 32.72 270 top
PR83  2D2R5J-1-GP  [R805H24]  130.4 51.31 90 top
PR84  470KR2F-GP  [R402H16]  131.86 45.04 90 top
PR85  10KR2F-2-GP  [R402H16]  130.99 43.41 0 top
PR86  0R2J-2-GP  [R402H16]  128.91 43.43 180 top
PR87  11K5R2F-GP  [R402H16]  129.95 43.41 180 top
